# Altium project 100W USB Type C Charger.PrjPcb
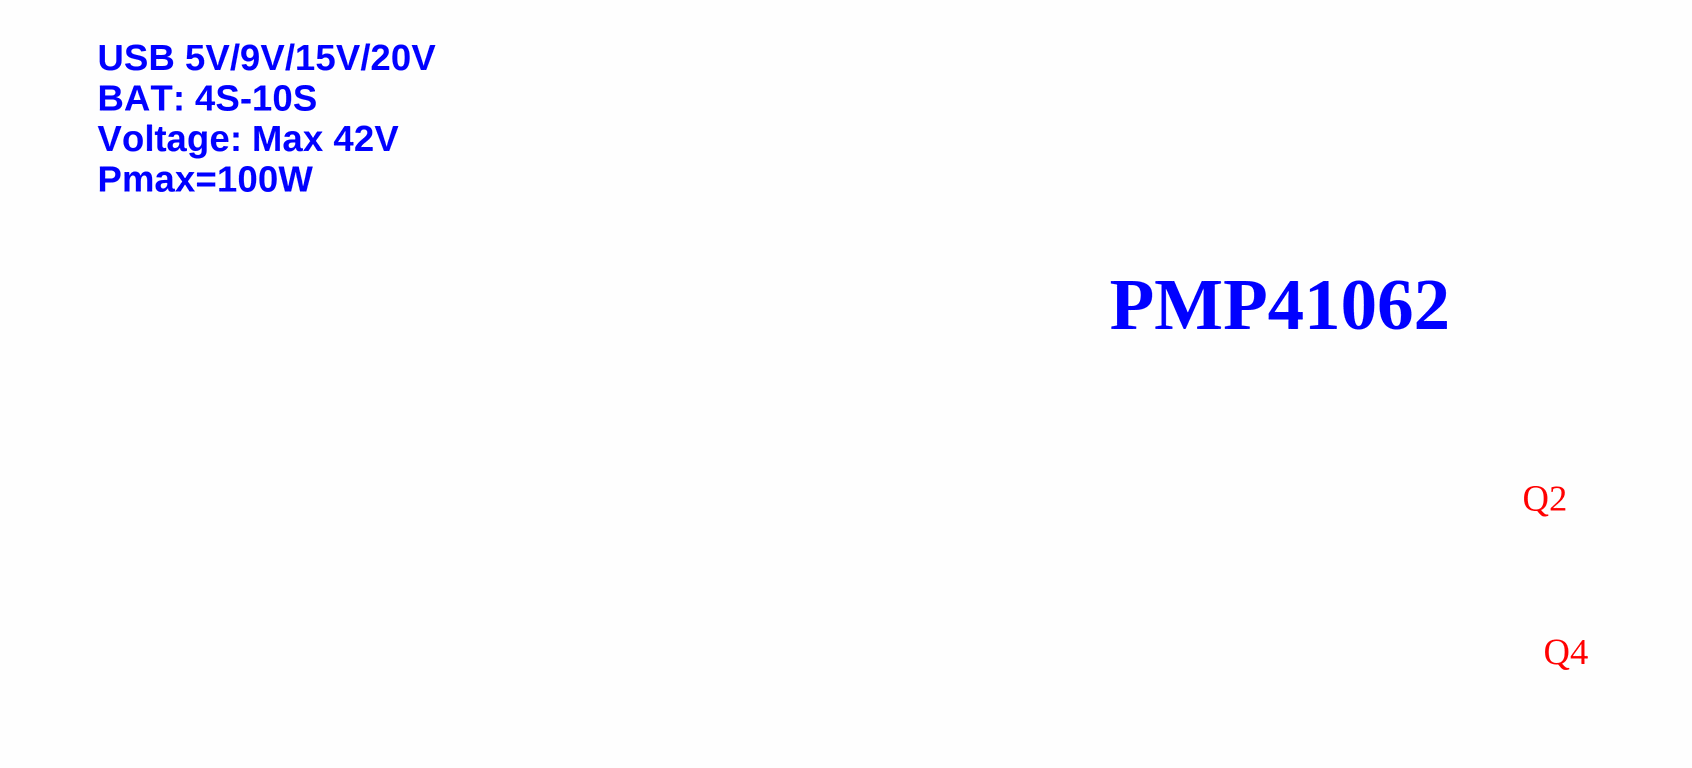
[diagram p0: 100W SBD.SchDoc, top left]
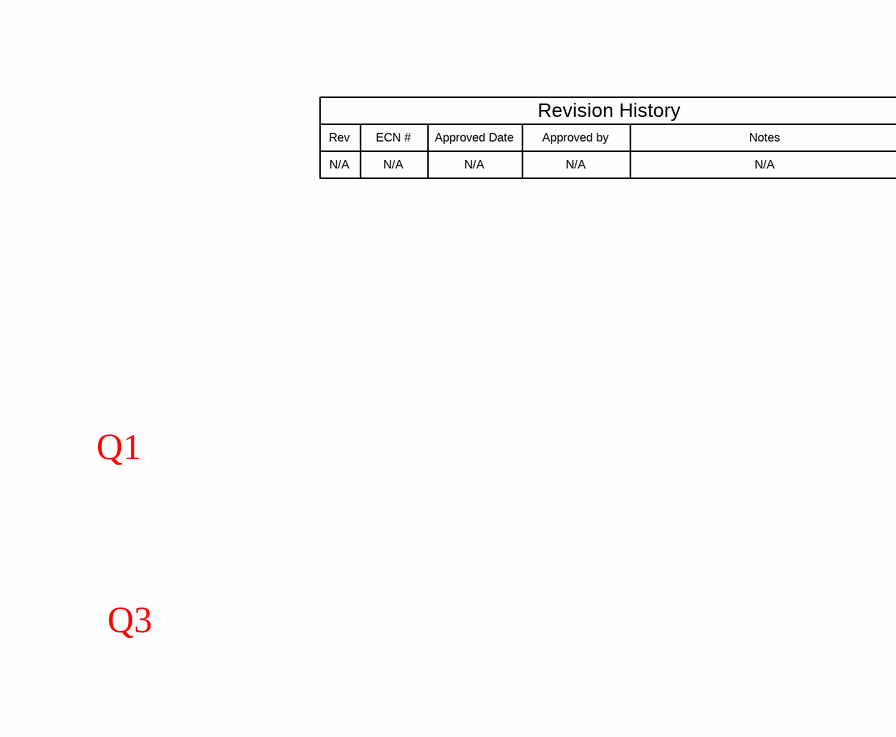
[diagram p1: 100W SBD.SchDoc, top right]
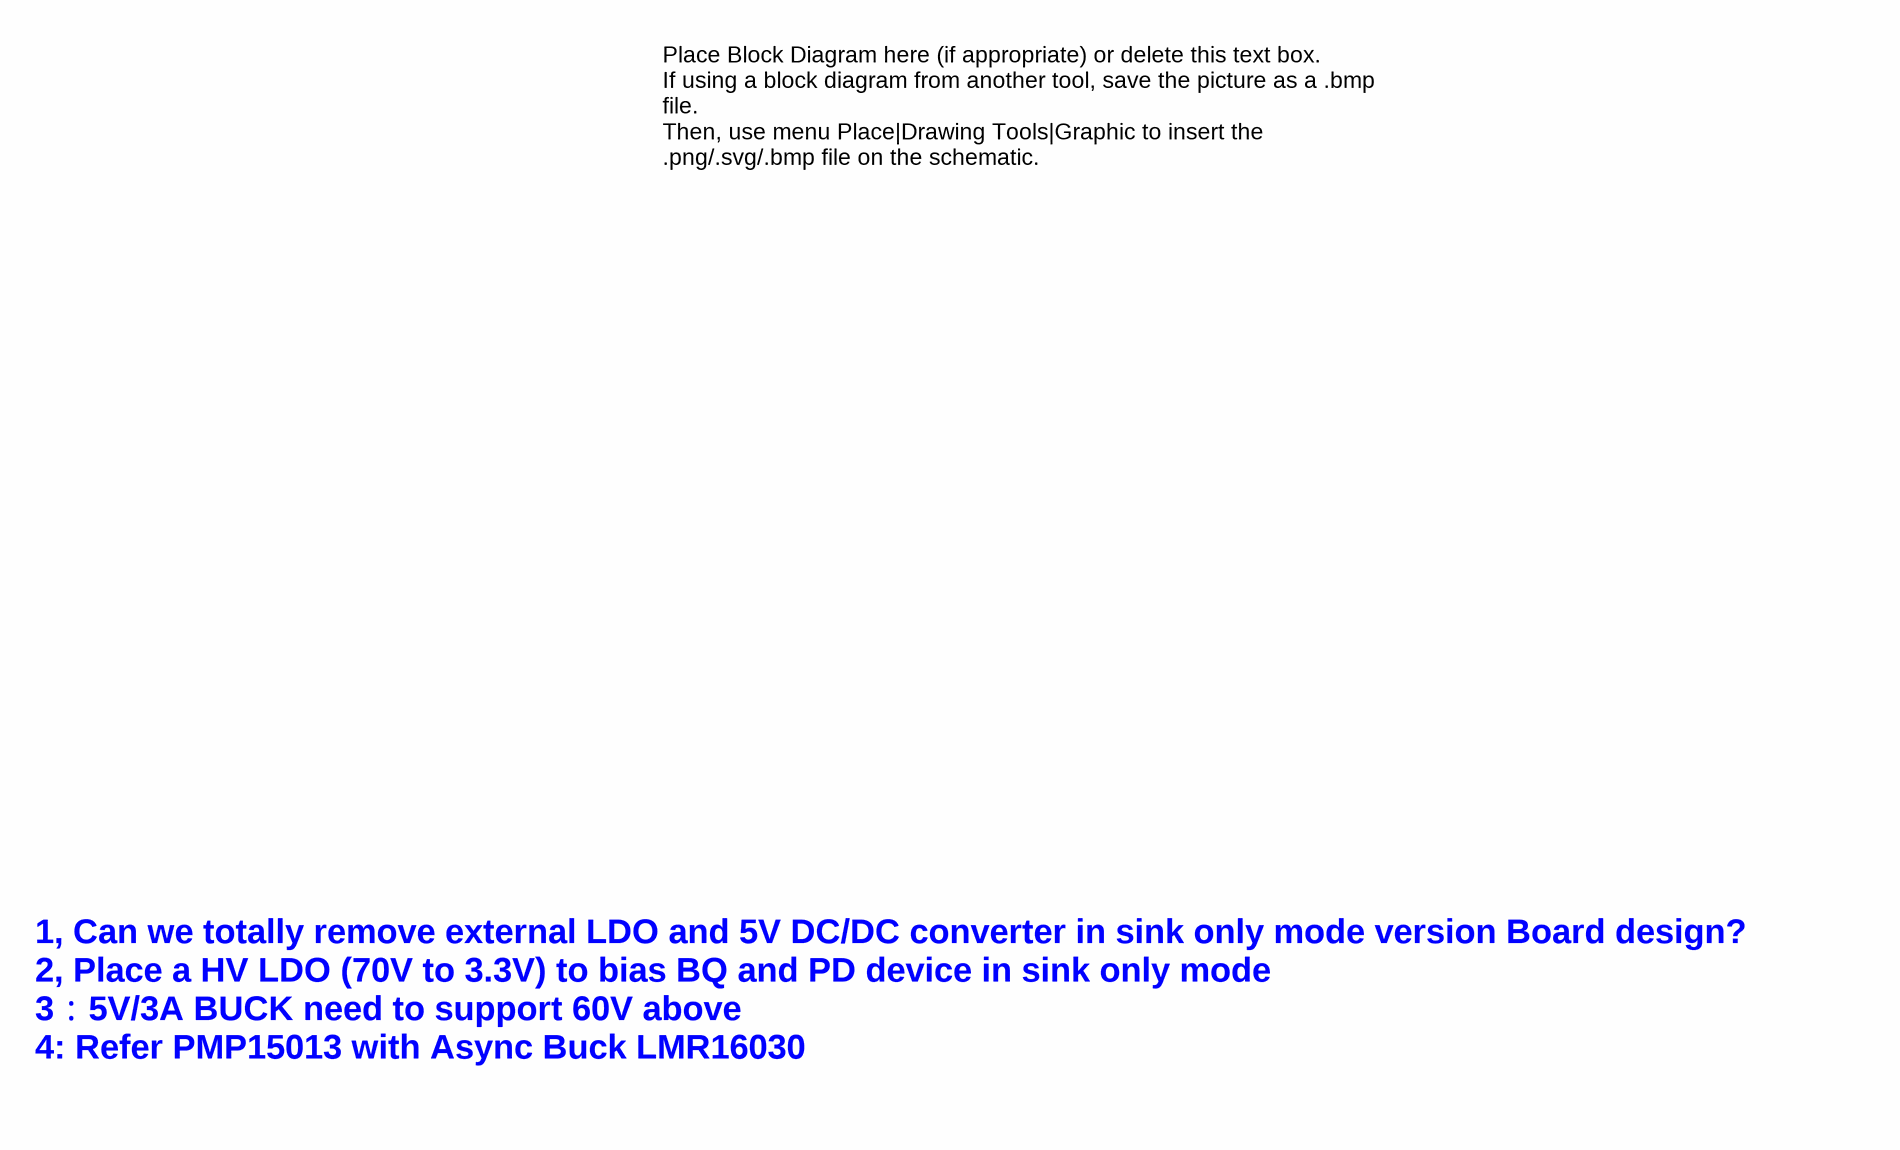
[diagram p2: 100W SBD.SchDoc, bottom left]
CopyrightYear: 2018; PCB_Layout: Max Wang; PCB_Rev: E1; PRJ_Customer: Public Release; PRJ_Engineer: Max Wang; PRJ_Number: PMP41062; PRJ_Title: 100W USB Type C; SCH_Rev: E1; TechSupport: http://www.ti.com/support; TID: PMP41062
4 sheets, 162 parts. Net scope: flat (ports and power ports of the same name join across sheets).
Board file: 100W USB Type C Charger.PcbDoc
Sheets:
  100W SBD.SchDoc
  PD Controller.SchDoc
  Charger BQ25756.SchDoc
  100W USB Type C Charger_Hardware.SchDoc

## Sheet 100W SBD.SchDoc
size A2; Date: Not shown in title block; ApprovedBy: Not shown in title block; CheckedBy: Not shown in title block; Author: Not shown in title block; CompanyName: Not shown in title block; Engineer: Not shown in title block; Organization: Not shown in title block; Address1: Not shown in title block; Address2: Not shown in title block; Address3: Not shown in title block; Address4: Not shown in title block; DocumentNumber: 1; Revision: Use project parameter SCH_Rev; SheetNumber: 1; SheetTotal: 4; PageSetup: Record=PageOptions¦CenterHorizontal=True¦CenterVertical=True¦PrintScale=1.00¦XCorrection=1.00¦YCorrection=1.00¦PrintKind=0¦BorderSize=5000000¦LeftOffset=0¦BottomOffset=0¦Orientation=2¦PaperLength=1000¦PaperWidth=1000¦Scale=100¦PaperSource=15¦PrintQuality=600¦MediaType=1¦DitherType=10¦PaperKind=Letter¦PrintScaleMode=1

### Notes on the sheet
- Revision History
- USB 5V/9V/15V/20V
  BAT: 4S-10S
  Voltage: Max 42V
  Pmax=100W
- Rev
- N/A
- ECN #
- Approved Date
- Approved by
- Notes
- PMP41062
- Q1
- Q2
- Q4
- Q3
- Place Block Diagram here (if appropriate) or delete this text box.
  If using a block diagram from another tool, save the picture as a .bmp file.
  Then, use menu Place|Drawing Tools|Graphic to insert the .png/.svg/.bmp file on the schematic.
- 1, Can we totally remove external LDO and 5V DC/DC converter in sink only mode version Board design?
  2, Place a HV LDO (70V to 3.3V) to bias BQ and PD device in sink only mode
  3：5V/3A BUCK need to support 60V above
  4: Refer PMP15013 with Async Buck LMR16030

## Sheet PD Controller.SchDoc
size A2; Date: Not shown in title block; ApprovedBy: Not shown in title block; CheckedBy: Not shown in title block; Author: Not shown in title block; CompanyName: Not shown in title block; Engineer: Not shown in title block; Organization: Not shown in title block; Address1: Not shown in title block; Address2: Not shown in title block; Address3: Not shown in title block; Address4: Not shown in title block; DocumentNumber: 1; Revision: Use project parameter SCH_Rev; SheetNumber: 2; SheetTotal: 4; PageSetup: Record=PageOptions¦CenterHorizontal=True¦CenterVertical=True¦PrintScale=1.00¦XCorrection=1.00¦YCorrection=1.00¦PrintKind=0¦BorderSize=5000000¦LeftOffset=0¦BottomOffset=0¦Orientation=2¦PaperLength=1000¦PaperWidth=1000¦Scale=100¦PaperSource=15¦PrintQuality=600¦MediaType=1¦DitherType=10¦PaperKind=Letter¦PrintScaleMode=1
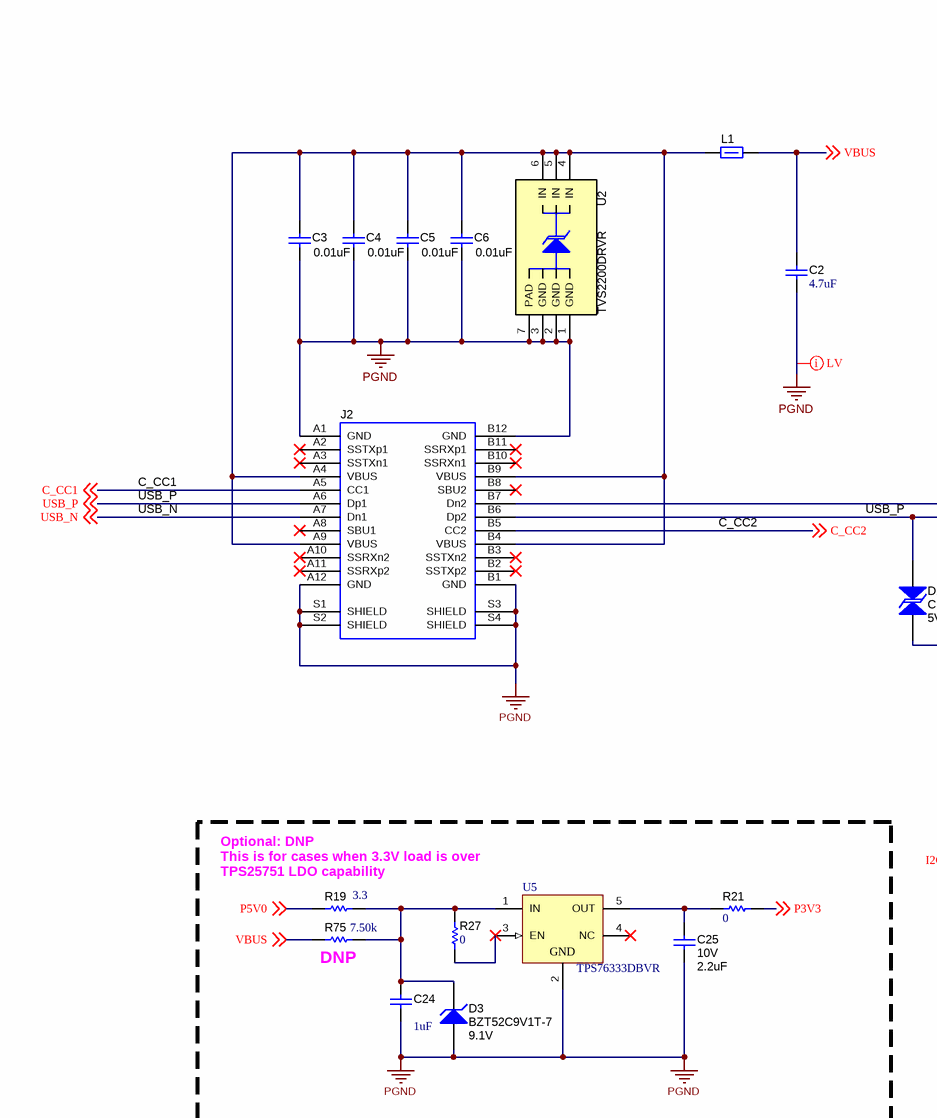
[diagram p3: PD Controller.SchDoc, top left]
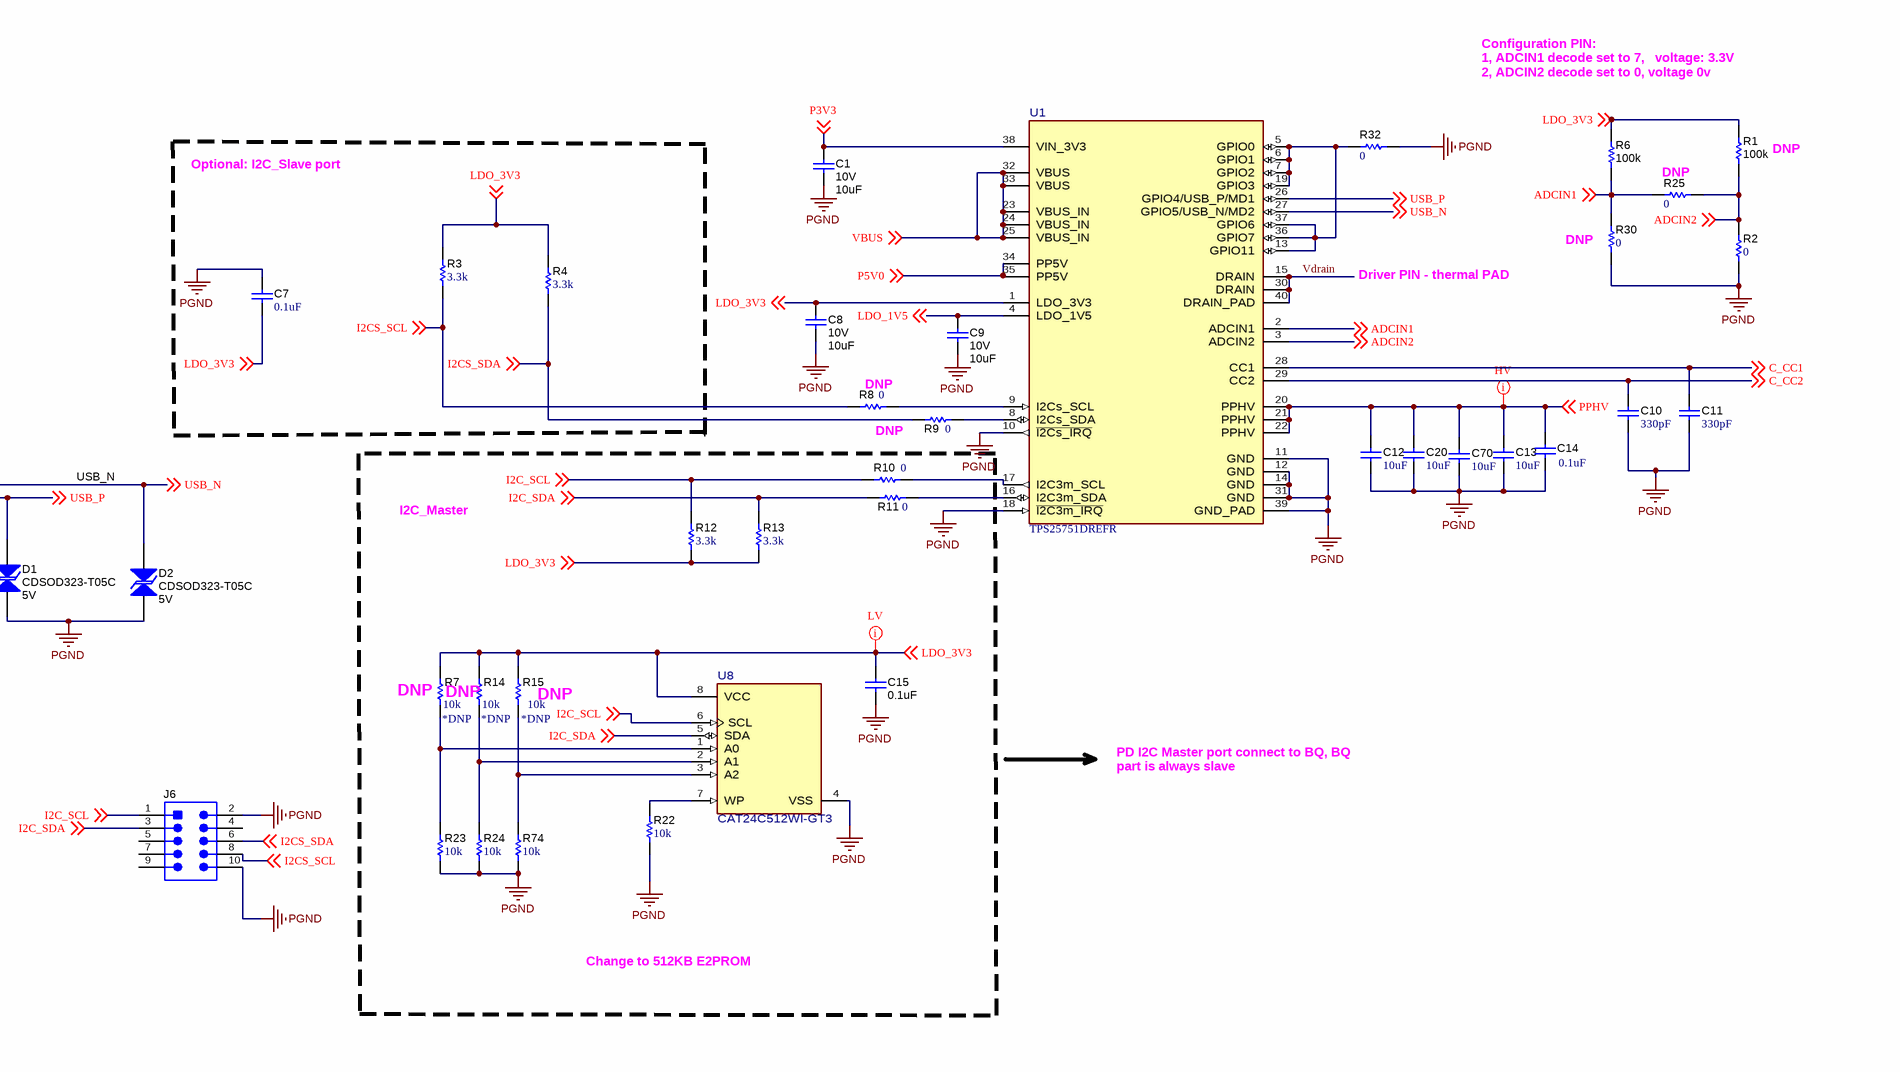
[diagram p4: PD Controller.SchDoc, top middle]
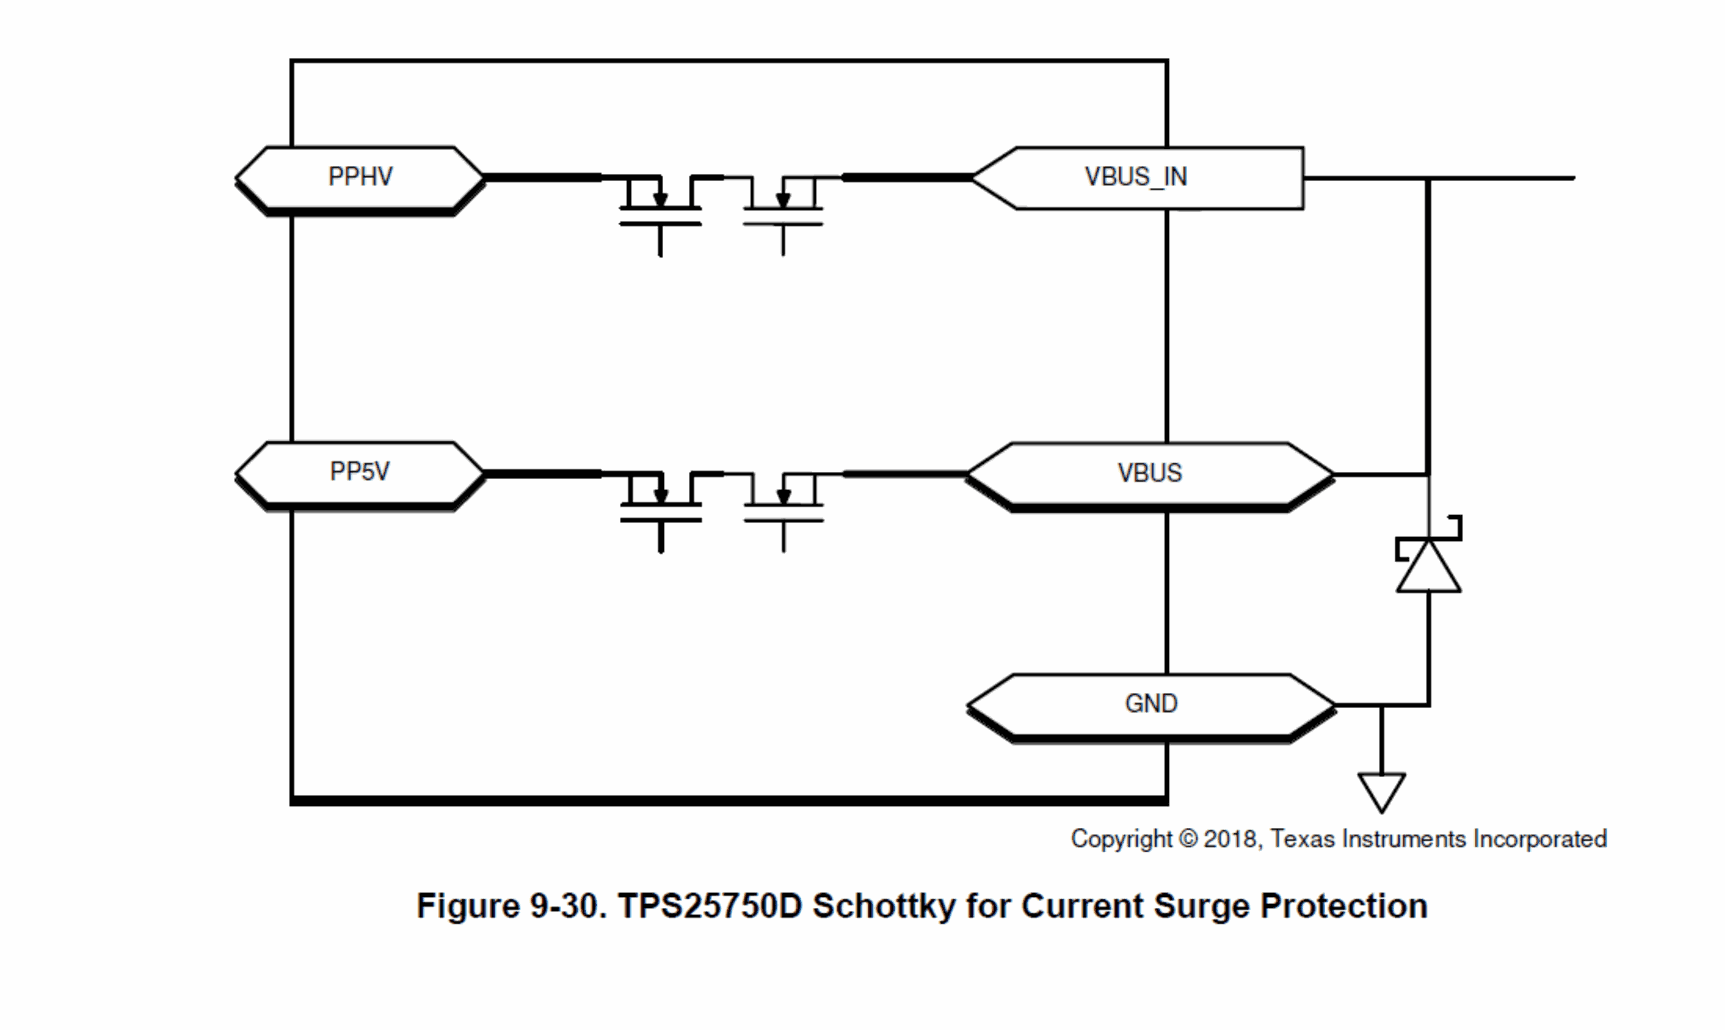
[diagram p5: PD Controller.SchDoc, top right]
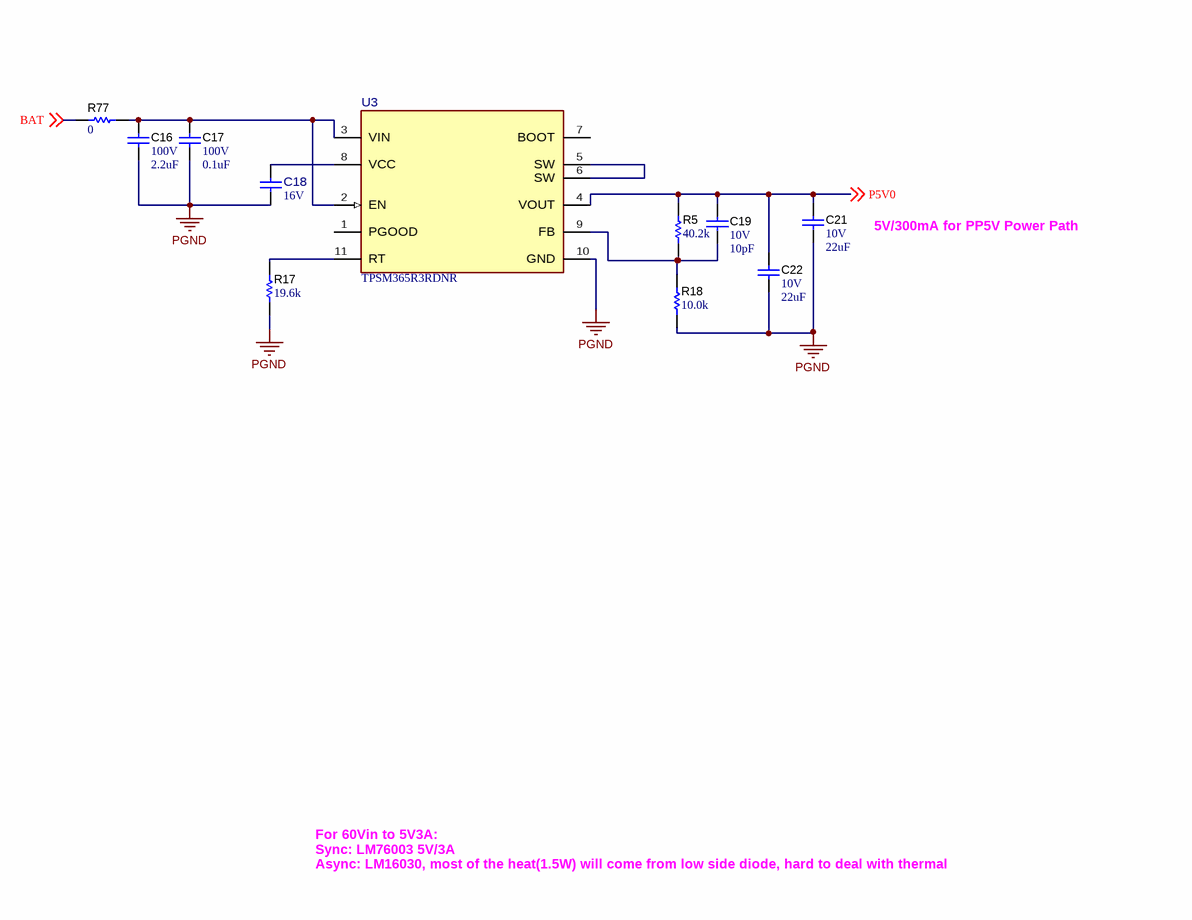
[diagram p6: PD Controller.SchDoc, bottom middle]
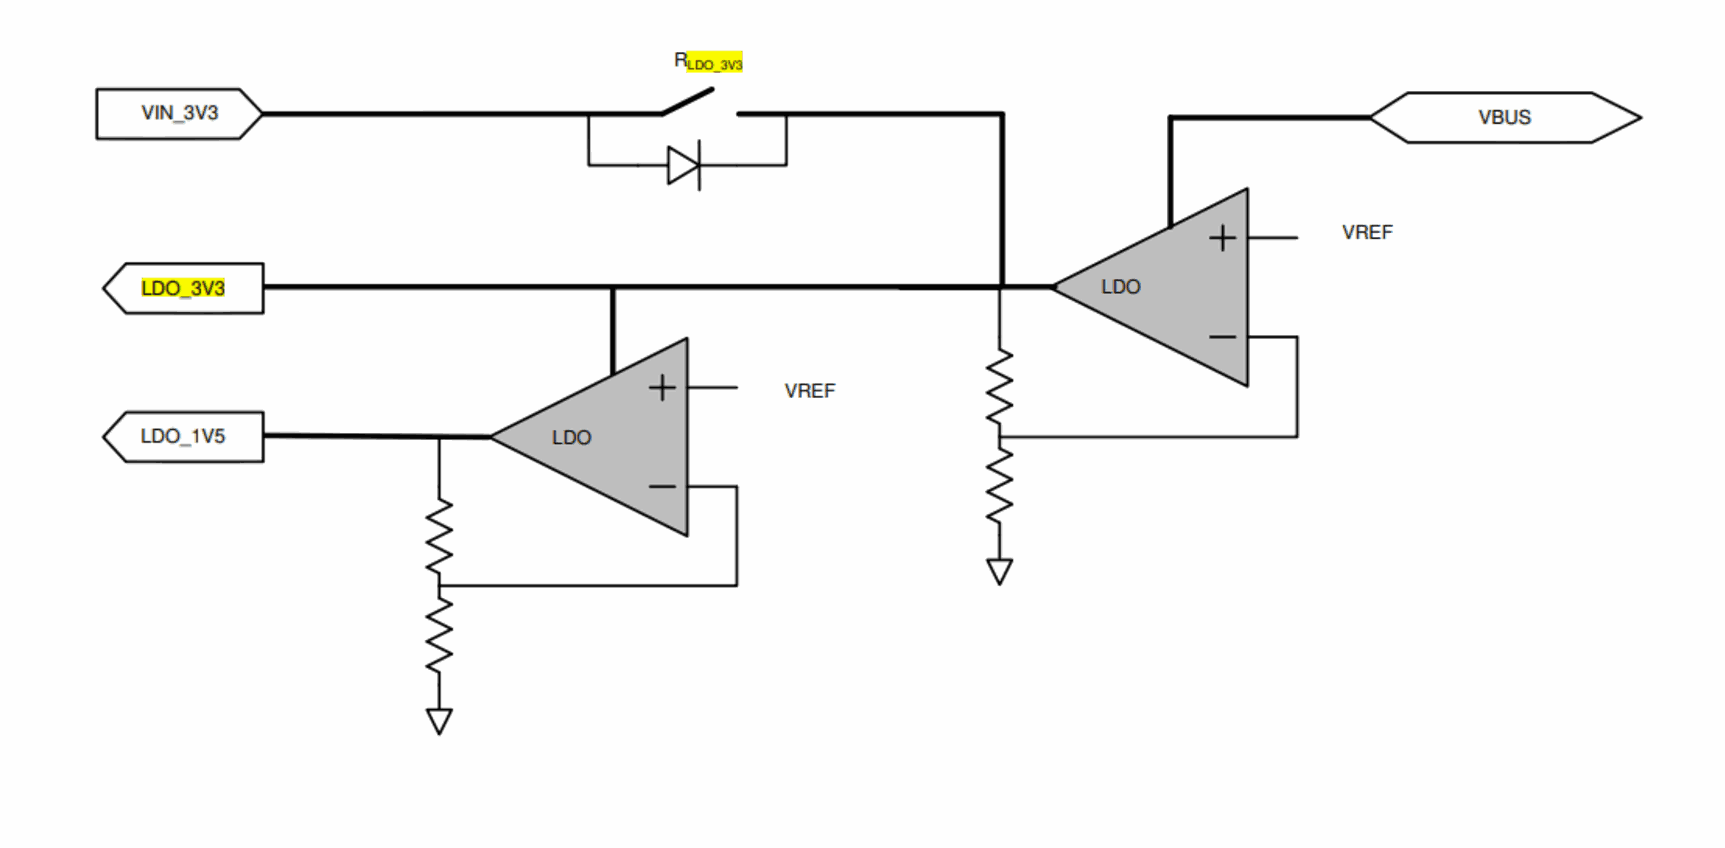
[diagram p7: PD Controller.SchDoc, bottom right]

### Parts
C1  VDC_V: 10V  ValueDisplayed: 10uF  [0402_070]  (hidden comment: CL05A106MP5NUNC)
C2  ValueDisplayed: 4.7uF  [0805_HV]  (hidden comment: GRM21BR61H475KE51L)
C3  ValueDisplayed: 0.01uF  [0402]  (hidden comment: C0402C103J5RACTU)
C4  ValueDisplayed: 0.01uF  [0402]  (hidden comment: C0402C103J5RACTU)
C5  ValueDisplayed: 0.01uF  [0402]  (hidden comment: C0402C103J5RACTU)
C6  ValueDisplayed: 0.01uF  [0402]  (hidden comment: C0402C103J5RACTU)
C7  ValueDisplayed: 0.1uF  [0603]  (hidden comment: CMP-0006808-4)
C8  VDC_V: 10V  ValueDisplayed: 10uF  [0402_070]  (hidden comment: CL05A106MP5NUNC)
C9  VDC_V: 10V  ValueDisplayed: 10uF  [0402_070]  (hidden comment: CL05A106MP5NUNC)
C10  ValueDisplayed: 330pF  [0201_033]  (hidden comment: CGA1A2X7R1H331K030BA)
C11  ValueDisplayed: 330pF  [0201_033]  (hidden comment: CGA1A2X7R1H331K030BA)
C12  ValueDisplayed: 10uF  [1206_180]  (hidden comment: CL31B106KBHNNNE)
C13  ValueDisplayed: 10uF  [1206_180]  (hidden comment: CL31B106KBHNNNE)
C14  ValueDisplayed: 0.1uF  [0603]  (hidden comment: GCM188R71H104KA57D)
C15  ValueDisplayed: 0.1uF  [0402]  (hidden comment: GMK105BJ104KV-F)
C16  VDC_V: 100V  ValueDisplayed: 2.2uF  [1206_180]  (hidden comment: C3216X7S2A225K160AB)
C17  VDC_V: 100V  ValueDisplayed: 0.1uF  [0402]  (hidden comment: GRM155R62A104KE14D)
C18  VDC_V: 16V  [FP-0402YD105KAT2A_0402-IPC_B]  (hidden comment: 0402YD105KAT2A)
C19  VDC_V: 10V  ValueDisplayed: 10pF  [0402]  (hidden comment: C0402C100C8GACTU)
C20  ValueDisplayed: 10uF  [1206_180]  (hidden comment: CL31B106KBHNNNE)
C21  VDC_V: 10V  ValueDisplayed: 22uF  [0603]  (hidden comment: CL10A226MP8NUNE)
C22  VDC_V: 10V  ValueDisplayed: 22uF  [0603]  (hidden comment: CL10A226MP8NUNE)
C24  ValueDisplayed: 1uF  [0805_HV]  (hidden comment: C2012X7S2A105K125AB)
C25  VDC_V: 10V  ValueDisplayed: 2.2uF  [0603]  (hidden comment: CGA3E3X5R1A225K080AB)
C70  ValueDisplayed: 10uF  [1206_180]  (hidden comment: CL31B106KBHNNNE)
D1  CDSOD323-T05C  value 5V  [SOD-323-Bi]
D2  CDSOD323-T05C  value 5V  [SOD-323-Bi]
D3  BZT52C9V1T-7  value 9.1V  [SOD-523]
J2  DX07S024JJ2R1300  [JAE_DX07S024JJ2R1300]  (value not drawn)
J6  PEC05DAAN  [CONN_PEC05DAAN]  (value not drawn)
L1  FBMJ2125HM210NT  [0805_HV]  (value not drawn)
R1  ValueDisplayed: 100k  [0402]  (hidden comment: RMCF0402FT100K)
R2  ValueDisplayed: 0  [0402]  (hidden comment: RC0402JR-070RL)
R3  ValueDisplayed: 3.3k  [0402]  (hidden comment: CRCW04023K30JNED)
R4  ValueDisplayed: 3.3k  [0402]  (hidden comment: CRCW04023K30JNED)
R5  ValueDisplayed: 40.2k  [0603]  (hidden comment: RG1608P-4022-B-T5)
R6  ValueDisplayed: 100k  [0402]  (hidden comment: RMCF0402FT100K)
R7  value 10k  Parameter 1: *DNP  [0402]  (hidden comment: CMP-0026825-5)
R8  ValueDisplayed: 0  [0402]  (hidden comment: CMP-0027004-2)
R9  ValueDisplayed: 0  [0402]  (hidden comment: CMP-0027004-2)
R10  ValueDisplayed: 0  [0402]  (hidden comment: CMP-0027004-2)
R11  ValueDisplayed: 0  [0402]  (hidden comment: CMP-0027004-2)
R12  ValueDisplayed: 3.3k  [0402]  (hidden comment: CRCW04023K30JNED)
R13  ValueDisplayed: 3.3k  [0402]  (hidden comment: CRCW04023K30JNED)
R14  value 10k  Parameter 1: *DNP  [0402]  (hidden comment: CMP-0026825-5)
R15  value 10k  Parameter 1: *DNP  [0402]  (hidden comment: CMP-0026825-5)
R17  ValueDisplayed: 19.6k  [0402]  (hidden comment: CRCW040219K6FKED)
R18  ValueDisplayed: 10.0k  [0402]  (hidden comment: ERJ-2RKF1002X)
R19  ValueDisplayed: 3.3  [0805_HV]  (hidden comment: RC0805JR-073R3L)
R21  ValueDisplayed: 0  [0402]  (hidden comment: CMP-0027004-2)
R22  ValueDisplayed: 10k  [0402]  (hidden comment: CMP-0026825-5)
R23  ValueDisplayed: 10k  [0402]  (hidden comment: CMP-0026825-5)
R24  ValueDisplayed: 10k  [0402]  (hidden comment: CMP-0026825-5)
R25  ValueDisplayed: 0  [0402]  (hidden comment: CMP-0027004-2)
R27  ValueDisplayed: 0  [0402]  (hidden comment: CMP-0027004-2)
R30  ValueDisplayed: 0  [0402]  (hidden comment: RC0402JR-070RL)
R32  ValueDisplayed: 0  [0402]  (hidden comment: RC0402JR-070RL)
R74  ValueDisplayed: 10k  [0402]  (hidden comment: CMP-0026825-5)
R75  ValueDisplayed: 7.50k  [1206]  (hidden comment: RC1206FR-077K5L)
R77  ValueDisplayed: 0  [0402]  (hidden comment: CMP-0027004-2)
U1  TPS25751DREFR  [RJK0038B-MFG]
U2  TVS2200DRVR  [DRV0006A]
U3  TPSM365R3RDNR  [RDN0011A-MFG]
U5  TPS76333DBVR  [DBV0005A_N]
U8  CAT24C512WI-GT3  [FP-CAT24C512WI-GT3_SOIC8-IPC_C]

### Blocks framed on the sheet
DNP: C24 C25 D3 R19 R21 R27 R75 U5

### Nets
PGND: C1.2 C2.2 C3.2 C4.2 C5.2 C6.2 C7.1 C8.1 C9.1 C10.2 C11.2 C12.2 C13.2 C14.2 C15.2 C16.2 C17.2 C18.2 C20.2 C21.2 C22.2 C24.2 C25.2 C70.2 D1.1 D2.1 D3.2(A) J2.A1(GND) J2.A12(GND) J2.B1(GND) J2.B12(GND) J2.S1(SHIELD) J2.S2(SHIELD) J2.S3(SHIELD) J2.S4(SHIELD) J6.2 J6.10 R2.1 R17.1 R18.1 R22.1 R23.1 R24.1 R30.1 R32.2 R74.1 U1.10(~{I2Cs_IRQ}) U1.11(GND) U1.12(GND) U1.14(GND) U1.18(~{I2C3m_IRQ}) U1.31(GND) U1.39(GND_PAD) U2.1(GND) U2.2(GND) U2.3(GND) U2.7(PAD) U3.10(GND) U5.2(GND) U8.4(VSS)
ADCIN1: R6.2 R25.2 R30.2 U1.2(ADCIN1) ; off-sheet ADCIN1
ADCIN2: R1.1 R2.2 R25.1 U1.3(ADCIN2) ; off-sheet ADCIN2
BAT: R77.2 ; off-sheet BAT
C_CC1: C11.1 J2.A5(CC1) U1.28(CC1) ; off-sheet C_CC1
C_CC2: C10.1 J2.B5(CC2) U1.29(CC2) ; off-sheet C_CC2
I2C_SCL: J6.1 R10.2 R12.2 U8.6(SCL) ; off-sheet I2C_SCL
I2C_SDA: J6.3 R11.2 R13.2 U8.5(SDA) ; off-sheet I2C_SDA
I2CS_SCL: J6.8 R3.1 R8.2 ; off-sheet I2CS_SCL
I2CS_SDA: J6.6 R4.1 R9.2 ; off-sheet I2CS_SDA
LDO_1V5: C9.2 U1.4(LDO_1V5) ; off-sheet LDO_1V5
LDO_3V3: C7.2 C8.2 C15.1 R1.2 R3.2 R4.2 R6.1 R7.2 R12.1 R13.1 R14.2 R15.2 U1.1(LDO_3V3) U8.8(VCC) ; off-sheet LDO_3V3
P3V3: C1.1 R21.1 U1.38(VIN_3V3) ; off-sheet P3V3
P5V0: C19.1 C21.1 C22.1 R5.2 R19.2 U1.34(PP5V) U1.35(PP5V) U3.4(VOUT) ; off-sheet P5V0
PPHV: C12.1 C13.1 C14.1 C20.1 C70.1 U1.20(PPHV) U1.21(PPHV) U1.22(PPHV) ; off-sheet PPHV
USB_N: D2.2 J2.A7(Dn1) J2.B7(Dn2) U1.27(GPIO5/USB_N/MD2) ; off-sheet USB_N
USB_P: D1.2 J2.A6(Dp1) J2.B6(Dp2) U1.26(GPIO4/USB_P/MD1) ; off-sheet USB_P
VBUS: C2.1 L1.2 R75.2 U1.23(VBUS_IN) U1.24(VBUS_IN) U1.25(VBUS_IN) U1.32(VBUS) U1.33(VBUS) ; off-sheet VBUS
Vdrain: U1.15(DRAIN) U1.30(DRAIN) U1.40(DRAIN_PAD)
NetC3_1: C3.1 C4.1 C5.1 C6.1 J2.A4(VBUS) J2.A9(VBUS) J2.B4(VBUS) J2.B9(VBUS) L1.1 U2.4(IN) U2.5(IN) U2.6(IN)
NetC16_1: C16.1 C17.1 R77.1 U3.2(EN) U3.3(VIN)
NetC18_1: C18.1 U3.8(VCC)
NetC19_2: C19.2 R5.1 R18.2 U3.9(FB)
NetC24_1: C24.1 D3.1(K) R19.1 R27.2 R75.1 U5.1(IN)
NetC25_1: C25.1 R21.2 U5.5(OUT)
NetR7_1: R7.1 R23.2 U8.1(A0)
NetR8_1: R8.1 U1.9(I2Cs_SCL)
NetR9_1: R9.1 U1.8(I2Cs_SDA)
NetR10_1: R10.1 U1.17(I2C3m_SCL)
NetR11_1: R11.1 U1.16(I2C3m_SDA)
NetR14_1: R14.1 R24.2 U8.2(A1)
NetR15_1: R15.1 R74.2 U8.3(A2)
NetR17_2: R17.2 U3.11(RT)
NetR22_2: R22.2 U8.7(WP)
NetR27_1: R27.1 U5.3(EN)
NetR32_1: R32.1 U1.5(GPIO0) U1.6(GPIO1) U1.7(GPIO2) U1.13(GPIO11) U1.19(GPIO3) U1.36(GPIO7) U1.37(GPIO6)
NetU3_5: U3.5(SW) U3.6(SW)

Not connected (* = marked no-connect by the designer): J2 A2(SSTXp1)* A3(SSTXn1)* A8(SBU1)* A10(SSRXn2)* A11(SSRXp2)* B2(SSTXp2)* B3(SSTXn2)* B8(SBU2)* B10(SSRXn1)* B11(SSRXp1)*; J6 4 5 7 9; U3 1(PGOOD) 7(BOOT); U5 4(NC)*

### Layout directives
net class LV: LDO_3V3, PGND
net class HV: PPHV

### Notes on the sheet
- Configuration PIN:
  1, ADCIN1 decode set to 7,   voltage: 3.3V
  2, ADCIN2 decode set to 0, voltage 0v
- Optional: I2C_Slave port
- (near R25) DNP
- (near R1) DNP
- (near R30) DNP
- Driver PIN - thermal PAD
- (near R8) DNP
- (near R9) DNP
- I2C_Master
- (near R7) DNP
- (near R14) DNP
- (near R15) DNP
- PD I2C Master port connect to BQ, BQ part is always slave
- Optional: DNP
  This is for cases when 3.3V load is over TPS25751 LDO capability
- Change to 512KB E2PROM
- 5V/300mA for PP5V Power Path
- For 60Vin to 5V3A:
  Sync: LM76003 5V/3A
  Async: LM16030, most of the heat(1.5W) will come from low side diode, hard to deal with thermal

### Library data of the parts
C1 C8 C9 = CMP-0006339-4: CAP, CERM, 10 uF, 10 V, +/- 20%, X5R, 0402; Manufacturer: Samsung Electro-Mechanics; TaMin_C: -55°C; Polarized: N; SizeAreaWB_mm2: 3; Value1: Unknown; U/M: EA; Value: 10uF; TaMax_C: 85°C; SizeZ_mm: 0.6; SizeX_mm: 1; SizeY_mm: 0.5; Cap_Case: 0402; Cap_F: 10µF; AEC Category: Q200
C2 = CMP-0008309-2: CAP, CERM, 4.7 uF, 50 V, +/- 10%, X5R, 0805; Manufacturer: MuRata; TaMin_C: -55°C; Polarized: N; SizeAreaWB_mm2: 6.75; Value1: Unknown; U/M: EA; Value: 4.7uF; TaMax_C: 85°C; SizeZ_mm: 1.45; SizeX_mm: 2; SizeY_mm: 1.25; Cap_Case: 0805; Value2: 50V; SizeArea_mm2: 2.5; Cap_F: 4.7µF; AEC Category: Q200
C3-C6 = CMP-0006236-2: CAP, CERM, 0.01 uF, 50 V, +/- 5%, X7R, 0402; Manufacturer: Kemet; TaMin_C: -55°C; Polarized: N; SizeAreaWB_mm2: 3; Value1: Unknown; U/M: EA; Value: 0.01uF; TaMax_C: 125°C; SizeZ_mm: 0.6; SizeX_mm: 1; SizeY_mm: 0.5; Value2: 50V; CompType: Capacitor; Cap_F: 10nF; AEC Category: Q200
C7 = CMP-0006808-4: CAP, CERM, 0.1 uF, 16 V, +/- 5%, X7R, 0603; PartNumber: 0603YC104JAT2A; Manufacturer: AVX; Polarized: N; Value: 0.1uF; U/M: EA; Cap_F: 100nF; ESR_ohm: 39m; Value1: 0.039 ohm; VDC_V: 16V; TaMin_C: -55°C; TaMax_C: 125°C; SizeArea_mm2: 1.28; SizeAreaWB_mm2: 4.68; SizeX_mm: 1.6; SizeY_mm: 0.8; SizeZ_mm: 1; AEC Category: Q200
C10 C11 = CMP-0009653-3: CAP, CERM, 330 pF, 50 V, +/- 10%, X7R, AEC-Q200 Grade 1, 0201; Manufacturer: TDK; TaMin_C: -55°C; ESR_ohm: 8.053; Polarized: N; SizeAreaWB_mm2: 2.08; Value1: 8.05302 ohm; U/M: EA; Value: 330pF; TaMax_C: 125°C; SizeZ_mm: 0.33; SizeX_mm: 0.6; SizeY_mm: 0.3; Value2: 50V; SizeArea_mm2: 0.18; AEC Qualified: Y; IRMS_A: 210.618mA; AEC Grade: 1; AEC Category: Q200
C12 C13 C20 C70 = CMP-0008802-2: CAP, CERM, 10 uF, 50 V, +/- 10%, X7R, 1206; Manufacturer: Samsung; TaMin_C: -55°C; Polarized: N; SizeAreaWB_mm2: 10.92; Value1: Unknown; U/M: EA; Value: 10uF; TaMax_C: 125°C; SizeZ_mm: 1.8; SizeX_mm: 3.2; SizeY_mm: 1.6; Cap_Case: 1206; Value2: 50V; SizeArea_mm2: 5.12; Cap_F: 10µF; AEC Category: Q200
C14 = CMP-0007144-4: CAP, CERM, 0.1 uF, 50 V, +/- 10%, X7R, 0603; Manufacturer: MuRata; TaMin_C: -55°C; Polarized: N; SizeAreaWB_mm2: 4.68; Value1: 0.02 ohm; U/M: EA; Value: 0.1uF; TaMax_C: 125°C; SizeZ_mm: 1; SizeX_mm: 1.6; SizeY_mm: 0.8; Value2: 50V; SizeArea_mm2: 1.28; Cap_F: 100nF; AEC Category: Q200; ESR_ohm: 20m; IRMS_A: 1.84A
C15 = CMP-0006370-2: CAP, CERM, 0.1 uF, 35 V, +/- 10%, X5R, 0402; Manufacturer: Taiyo Yuden; TaMin_C: -55°C; Polarized: N; SizeAreaWB_mm2: 3; Value1: Unknown; U/M: EA; Value: 0.1uF; TaMax_C: 85°C; SizeZ_mm: 0.6; SizeX_mm: 1; SizeY_mm: 0.5; Value2: 35V; CompType: Capacitor; Cap_F: 100nF; AEC Category: Q200
C16 = CMP-0008724-2: CAP, CERM, 2.2 uF, 100 V, +/- 10%, X7S, 1206; Manufacturer: TDK; TaMin_C: -55°C; ESR_ohm: 5.718m; Polarized: N; SizeAreaWB_mm2: 10.92; Value1: 0.005718 ohm; U/M: EA; Value: 2.2uF; TaMax_C: 125°C; SizeZ_mm: 1.8; SizeX_mm: 3.2; SizeY_mm: 1.6; SizeArea_mm2: 5.12; Cap_F: 2.2µF; IRMS_A: 3.0363A; AEC Category: Q200
C17 = CMP-0006618-1: CAP, CERM, 0.1 uF, 100 V, +/- 10%, X5R, 0402; Manufacturer: MuRata; TaMin_C: -55°C; Polarized: N; SizeAreaWB_mm2: 3; Value1: Unknown; U/M: EA; Value: 0.1uF; TaMax_C: 85°C; SizeZ_mm: 0.6; SizeX_mm: 1; SizeY_mm: 0.5; Cap_F: 100nF; AEC Category: Q200
C18 = CMP-00860000-2: CAPACITOR, X5R, 0402, 16V, 1UF; Manufacturer: AVX; SizeZ_mm: 0.56mm; Value: 1µF; TempCo: 15%; Tolerance_%: 10%; AEC Qualified: No; Symbol Name: SYM-0402YD105KAT2A
C19 = CMP-0064914-1: CAP, CERM, 10 pF, 10 V,+/- 2.5%, C0G/NP0, 0402; Manufacturer: Kemet; TaMin_C: -55°C; Polarized: N; SizeAreaWB_mm2: 3; Value1: Unknown; U/M: EA; Value: 10pF; TaMax_C: 125°C; SizeZ_mm: 0.6; SizeX_mm: 1; SizeY_mm: 0.5; AEC Category: Q200
C21 C22 = CMP-0007108-2: CAP, CERM, 22 uF, 10 V, +/- 20%, X5R, 0603; Manufacturer: Samsung Electro-Mechanics; TaMin_C: -55°C; Polarized: N; SizeAreaWB_mm2: 4.68; Value1: Unknown; U/M: EA; Value: 22uF; TaMax_C: 85°C; SizeZ_mm: 1; SizeX_mm: 1.6; SizeY_mm: 0.8; SizeArea_mm2: 1.28; Cap_F: 22µF; AEC Category: Q200
C24 = CMP-0007891-2: CAP, CERM, 1 uF, 100 V, +/- 10%, X7S, 0805; Manufacturer: TDK; TaMin_C: -55°C; Polarized: N; SizeAreaWB_mm2: 6.75; Value1: 0.008255 ohm; U/M: EA; Value: 1uF; TaMax_C: 125°C; SizeZ_mm: 1.45; SizeX_mm: 2; SizeY_mm: 1.25; Cap_Case: 0805; Value2: 100V; SizeArea_mm2: 2.5; Cap_F: 1µF; AEC Category: Q200; ESR_ohm: 8.255m; IRMS_A: 2.2744A
C25 = CMP-0007091-5: CAP, CERM, 2.2 uF, 10 V, +/- 10%, X5R, AEC-Q200 Grade 3, 0603; Manufacturer: TDK; TaMin_C: -55°C; Polarized: N; SizeAreaWB_mm2: 4.68; Value1: Unknown; U/M: EA; Value: 2.2uF; TaMax_C: 85°C; SizeZ_mm: 1; SizeX_mm: 1.6; SizeY_mm: 0.8; SizeArea_mm2: 1.28; AEC Qualified: Y; Cap_F: 2.2µF; AEC Grade: 3; AEC Category: Q200
D1 D2 = CMP-0006065-2: Diode, TVS, Bi, 5 V, SOD323, 2-Leads, Body 1.9x1.45mm, No Polarity Mark; Manufacturer: Bourns; Ppk: 350W; AEC Category: Q101
D3 = CMP-0005905-4: Diode, Zener, 9.1 V, 300 mW, SOD-523; Manufacturer: Diodes Inc.; SizeAreaWB_mm2: 5.13; RJA_CperW: 417; SizeZ_mm: 0.65; SizeArea_mm2: 1.53; AEC Category: Q101; Value1: 0.3W; SizeX_mm: 1.7; SizeY_mm: 0.9; Power_W: 300mW
J2 = CMP-0085712-2: Receptacle, USB 3.1 Type C, R/A, Gold, SMT; Manufacturer: JAE Electronics; Current_A: 1.25A; Gender: Female; Voltage_V: 20V; Pitch_mm: 0.5; Row_Count: 2
J6 = CMP-0054550-2: Header, 100mil, 5x2, Tin, TH; Manufacturer: Sullins Connector Solutions; Current_A: 3A; Green_Lifecycle: Active; Shrouded: N; Gender: Male; Green_REACh: Passed; Voltage_V: 1.8kV; Row_Count: 2; RowSpacing_mm: 2.54; Cert_UL: Y
L1 = CMP-0003375-1: Ferrite Bead, 21 ohm @ 100 MHz, 6 A, 0805; Manufacturer: Taiyo Yuden; ZTyp@100MHz_Ohm: 21; SizeAreaWB_mm2: 6.75; DCR_ohm: 4m; Value1: 0.004 ohm; Value: 21 ohm; Imax_A: 6A; SizeZ_mm: 1.45; SizeX_mm: 2; SizeY_mm: 1.25; SizeArea_mm2: 2.5
R1 R6 = CMP-0026753-1: RES, 100 k, 1%, 0.063 W, AEC-Q200 Grade 0, 0402; Manufacturer: Stackpole Electronics Inc; Power_W: 63mW; TempCo: 100 ppm/C; U/M: EA; Value: 100k; EIA_Code: E96; SizeX_mm: 1; SizeY_mm: 0.5; SizeZ_mm: 0.6; Value2: 0.063W; AEC Qualified: Y; VDC_V: 50V; AEC Grade: 0; AEC Category: Q200
R2 R30 R32 = CMP-0027004-1: RES, 0, 5%, 0.063 W, 0402; Manufacturer: Yageo America; Power_W: 63mW; TempCo: 200 ppm/C; Value_Code: 0000; U/M: EA; Value: 0; EIA_Code: E24; SizeX_mm: 1; SizeY_mm: 0.5; SizeZ_mm: 0.6; Value2: 0.063W; VDC_V: 50V; AEC Category: Q200
R3 R4 R12 R13 = CMP-0026918-5: RES, 3.3 k, 5%, 0.063 W, AEC-Q200 Grade 0, 0402; Manufacturer: Vishay-Dale; Value: 3.3k; Value_Code: 3k30; Power_W: 63mW; Value2: 0.063W; VDC_V: 50V; TempCo: 200 ppm/C; SizeArea_mm2: 0.5; SizeX_mm: 1; SizeZ_mm: 0.6; EIA_Code: E24; AEC Category: Q200; AEC Qualified: Y; AEC Grade: 0
R5 = CMP-0023541-1: RES, 40.2 k, 0.1%, 0.1 W, 0603; Manufacturer: Susumu Co Ltd; Power_W: 100mW; TempCo: 25 ppm/C; Value_Code: 40k2; U/M: EA; Value: 40.2k; EIA_Code: E192; SizeX_mm: 1.6; SizeY_mm: 0.8; SizeZ_mm: 1; Value2: 0.1W; SizeArea_mm2: 1.28; VDC_V: 75V; AEC Category: Q200
R7 R14 R15 = CMP-0026825-5: RES, 10 k, 5%, 0.063 W, AEC-Q200 Grade 0, 0402; PartNumber: CRCW040210K0JNED; Manufacturer: Vishay-Dale; Value_Code: 10k0; Power_W: 63mW; Value2: 0.063W; VDC_V: 50V; TempCo: 200 ppm/C; SizeArea_mm2: 0.5; SizeX_mm: 1; SizeZ_mm: 0.6; EIA_Code: E24; AEC Category: Q200; AEC Qualified: Y; AEC Grade: 0
R8-R11 R21 R25 R27 R77 = CMP-0027004-2: RES, 0, 5%, 0.063 W, 0402; PartNumber: RC0402JR-070RL; Manufacturer: Yageo America; Value: 0; Value_Code: 0000; Power_W: 63mW; Value2: 0.063W; VDC_V: 50V; TempCo: 200 ppm/C; SizeArea_mm2: 0.5; SizeX_mm: 1; SizeZ_mm: 0.6; EIA_Code: E24; U/M: EA; AEC Category: Q200
R17 = CMP-0026068-2: RES, 19.6 k, 1%, 0.063 W, 0402; Manufacturer: Vishay-Dale; Power_W: 63mW; TempCo: 100 ppm/C; Value_Code: 19k6; U/M: EA; Value: 19.6k; EIA_Code: E96; SizeX_mm: 1; SizeY_mm: 0.5; SizeZ_mm: 0.6; Value2: 0.063W; VDC_V: 50V; AEC Category: Q200
R18 = CMP-0026658-1: RES, 10.0 k, 1%, 0.1 W, 0402; Manufacturer: Panasonic; Power_W: 100mW; TempCo: 100 ppm/C; Value_Code: 10k0; U/M: EA; Value: 10.0k; EIA_Code: E96; Res_ohm: 10k; SizeX_mm: 1; SizeY_mm: 0.5; SizeZ_mm: 0.6; Value2: 0.1W; VDC_V: 50V; AEC Category: Q200
R19 = CMP-0020817-2: RES, 3.3, 5%, 0.125 W, 0805; Manufacturer: Yageo America; Value: 3.3; Value_Code: 3R30; Power_W: 125mW; Value2: 0.125W; VDC_V: 150V; TempCo: 200 ppm/C; SizeArea_mm2: 2.5; SizeX_mm: 2; SizeY_mm: 1.25; SizeZ_mm: 1.45; EIA_Code: E24; U/M: EA; AEC Category: Q200
R22-R24 R74 = CMP-0026825-5: RES, 10 k, 5%, 0.063 W, AEC-Q200 Grade 0, 0402; PartNumber: CRCW040210K0JNED; Manufacturer: Vishay-Dale; Value: 10k; Value_Code: 10k0; Power_W: 63mW; Value2: 0.063W; VDC_V: 50V; TempCo: 200 ppm/C; SizeArea_mm2: 0.5; SizeX_mm: 1; SizeZ_mm: 0.6; EIA_Code: E24; AEC Category: Q200; AEC Qualified: Y; AEC Grade: 0
R75 = CMP-0018483-2: RES, 7.50 k, 1%, 0.25 W, 1206; Manufacturer: Yageo America; Value: 7.50k; Res_ohm: 7.5k; Value_Code: 7k50; Power_W: 250mW; Value2: 0.25W; VDC_V: 200V; TempCo: 100 ppm/C; SizeArea_mm2: 5.12; SizeX_mm: 3.2; SizeY_mm: 1.6; SizeZ_mm: 1.35; EIA_Code: E96; U/M: EA; AEC Category: Q200
U1 = CMP-0098263-1: USB Type-C and USB PD Controller with Integrated Power Switches Optimized for Power Applications; Manufacturer: Texas Instruments; AEC Qualified: No; Usb Standard: USB 3.0; SizeZ_mm: 0.8mm; Number Of Ports: 1; Standoff Height: 0mm; Interface: I2C,USB
U2 = CMP-0077834-1: 22-V Precision Surge Protection Clamp, DRV0006A (WSON-6); Alternate Manufacturer: Texas Instruments; SizeAreaWB_mm2: 9.0; SizeZ_mm: 0.8; SizeX_mm: 2.0; SizeArea_mm2: 4.0; CompType: IC; AEC Qualified: N; AEC Category: Q200
U3 = CMP-0097147-1: 3-V to 65-V Input, 1-V to 13-V Output, 600-mA Synchronous Buck Converter Power Module in a HotRod QFN Package; Manufacturer: Texas Instruments; SizeZ_mm: 2.1mm; AEC Qualified: No; Max Duty Cycle: 98%; Max Supply Voltage: 65V; Min Supply Voltage: 3.6V; Nominal Supply Current: 17-18uA; Number Of Outputs: 1; Output Type: AdjustableProgrammable; Output Voltage: 1-13V; Standoff Height: 0mm; Switching Frequency: 200-2200kHz; TJmax_C: +125°C
U5 = CMP-0035539-1: Single Output LDO, 150 mA, Fixed 3.3 V Output, 2.7 to 10 V Input, with Low IQ, 5-pin SOT-23 (DBV), -40 to 125 degC, Green (RoHS & no Sb/Br); Manufacturer: Texas Instruments; Fixed Output Options(V): 3.3; SubFamily: Single Channel LDO; Vdo(Typ)(mV): 300; Accuracy(%): 3; Vin(Max)(V): 10; Iq(Typ)(mA): 0.08; Vin(Min)(V): 2.7; Iout(Max)(A): 0.15
U8 = CMP-0091847-1: EEPROM Memory IC 512Kb (64K x 8) I²C 1MHz 900ns 8-SOIC; Manufacturer: ON Semi; Standoff Height: 0.1mm; AEC Qualified: No; Max Supply Voltage: 5.5V; Interface: I2C; SizeZ_mm: 1.75mm; Memory Size: 512Kbits; Min Supply Voltage: 1.8V

## Sheet Charger BQ25756.SchDoc
size A2; Date: Not shown in title block; ApprovedBy: Not shown in title block; CheckedBy: Not shown in title block; Author: Not shown in title block; CompanyName: Not shown in title block; Engineer: Not shown in title block; Organization: Not shown in title block; Address1: Not shown in title block; Address2: Not shown in title block; Address3: Not shown in title block; Address4: Not shown in title block; DocumentNumber: 1; Revision: Use project parameter SCH_Rev; SheetNumber: 3; SheetTotal: 4; PageSetup: Record=PageOptions¦CenterHorizontal=True¦CenterVertical=True¦PrintScale=0.69¦XCorrection=1.00¦YCorrection=1.00¦PrintKind=0¦BorderSize=5000000¦LeftOffset=0¦BottomOffset=0¦Orientation=2¦PaperLength=1000¦PaperWidth=1000¦Scale=100¦PaperSource=15¦PrintQuality=600¦MediaType=1¦DitherType=10¦PaperKind=Letter¦PrintScaleMode=1
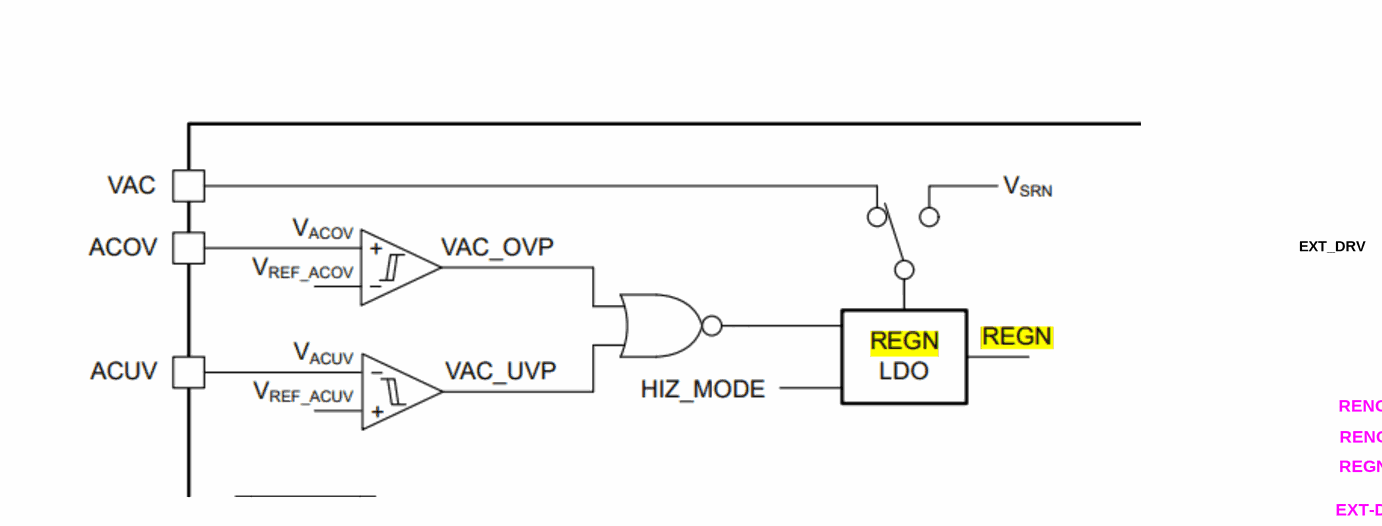
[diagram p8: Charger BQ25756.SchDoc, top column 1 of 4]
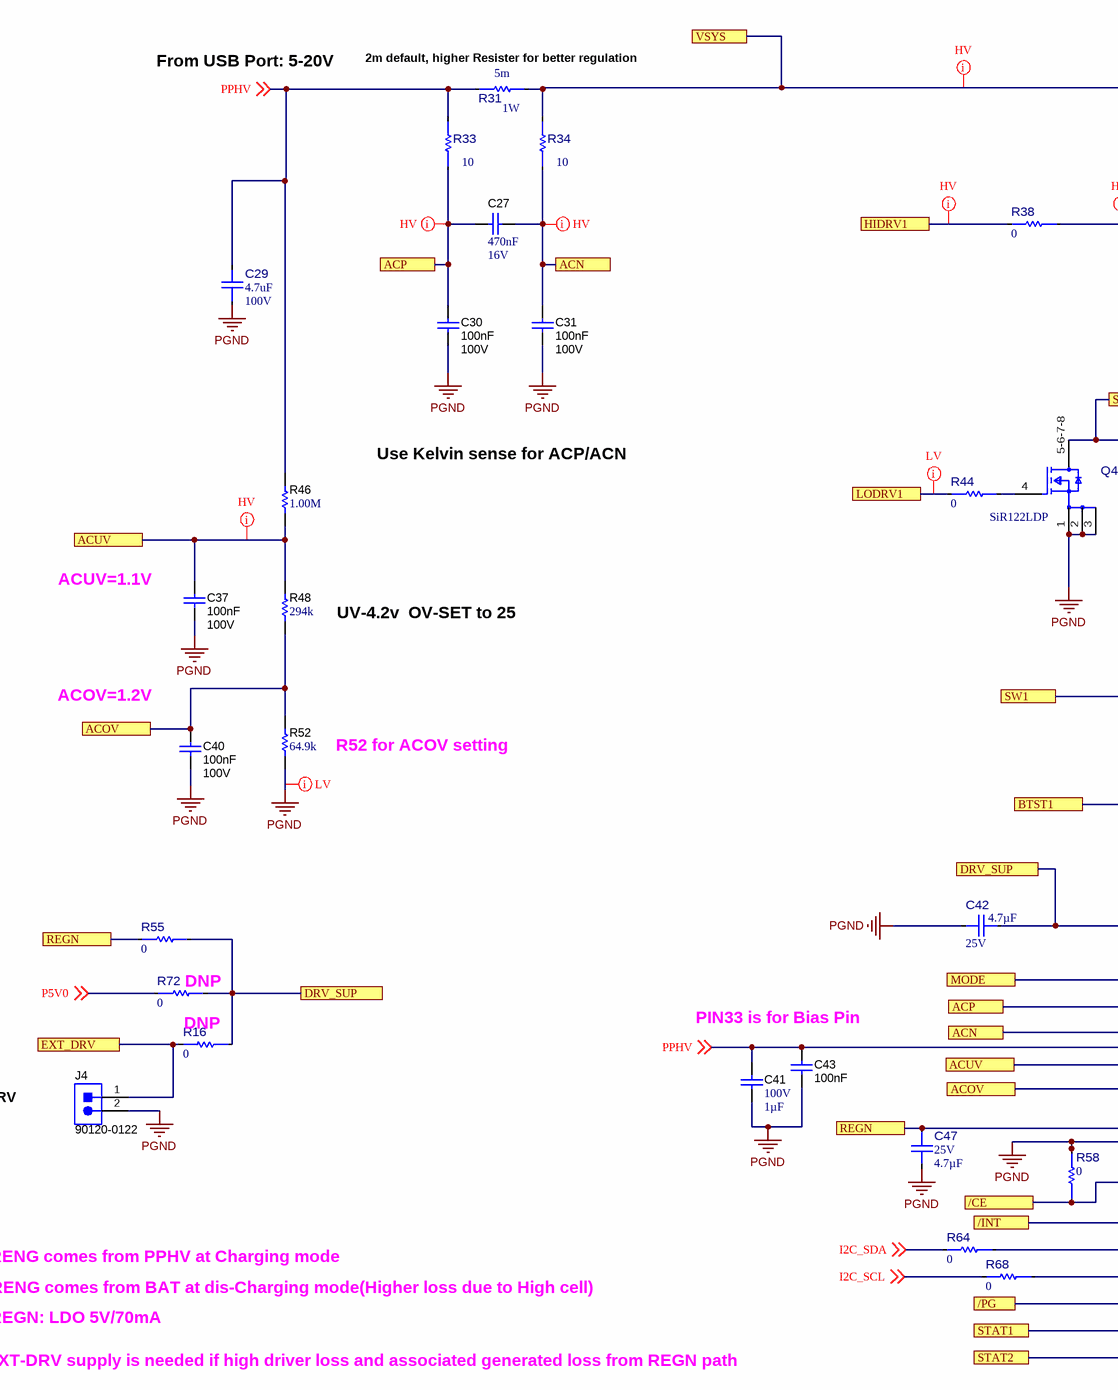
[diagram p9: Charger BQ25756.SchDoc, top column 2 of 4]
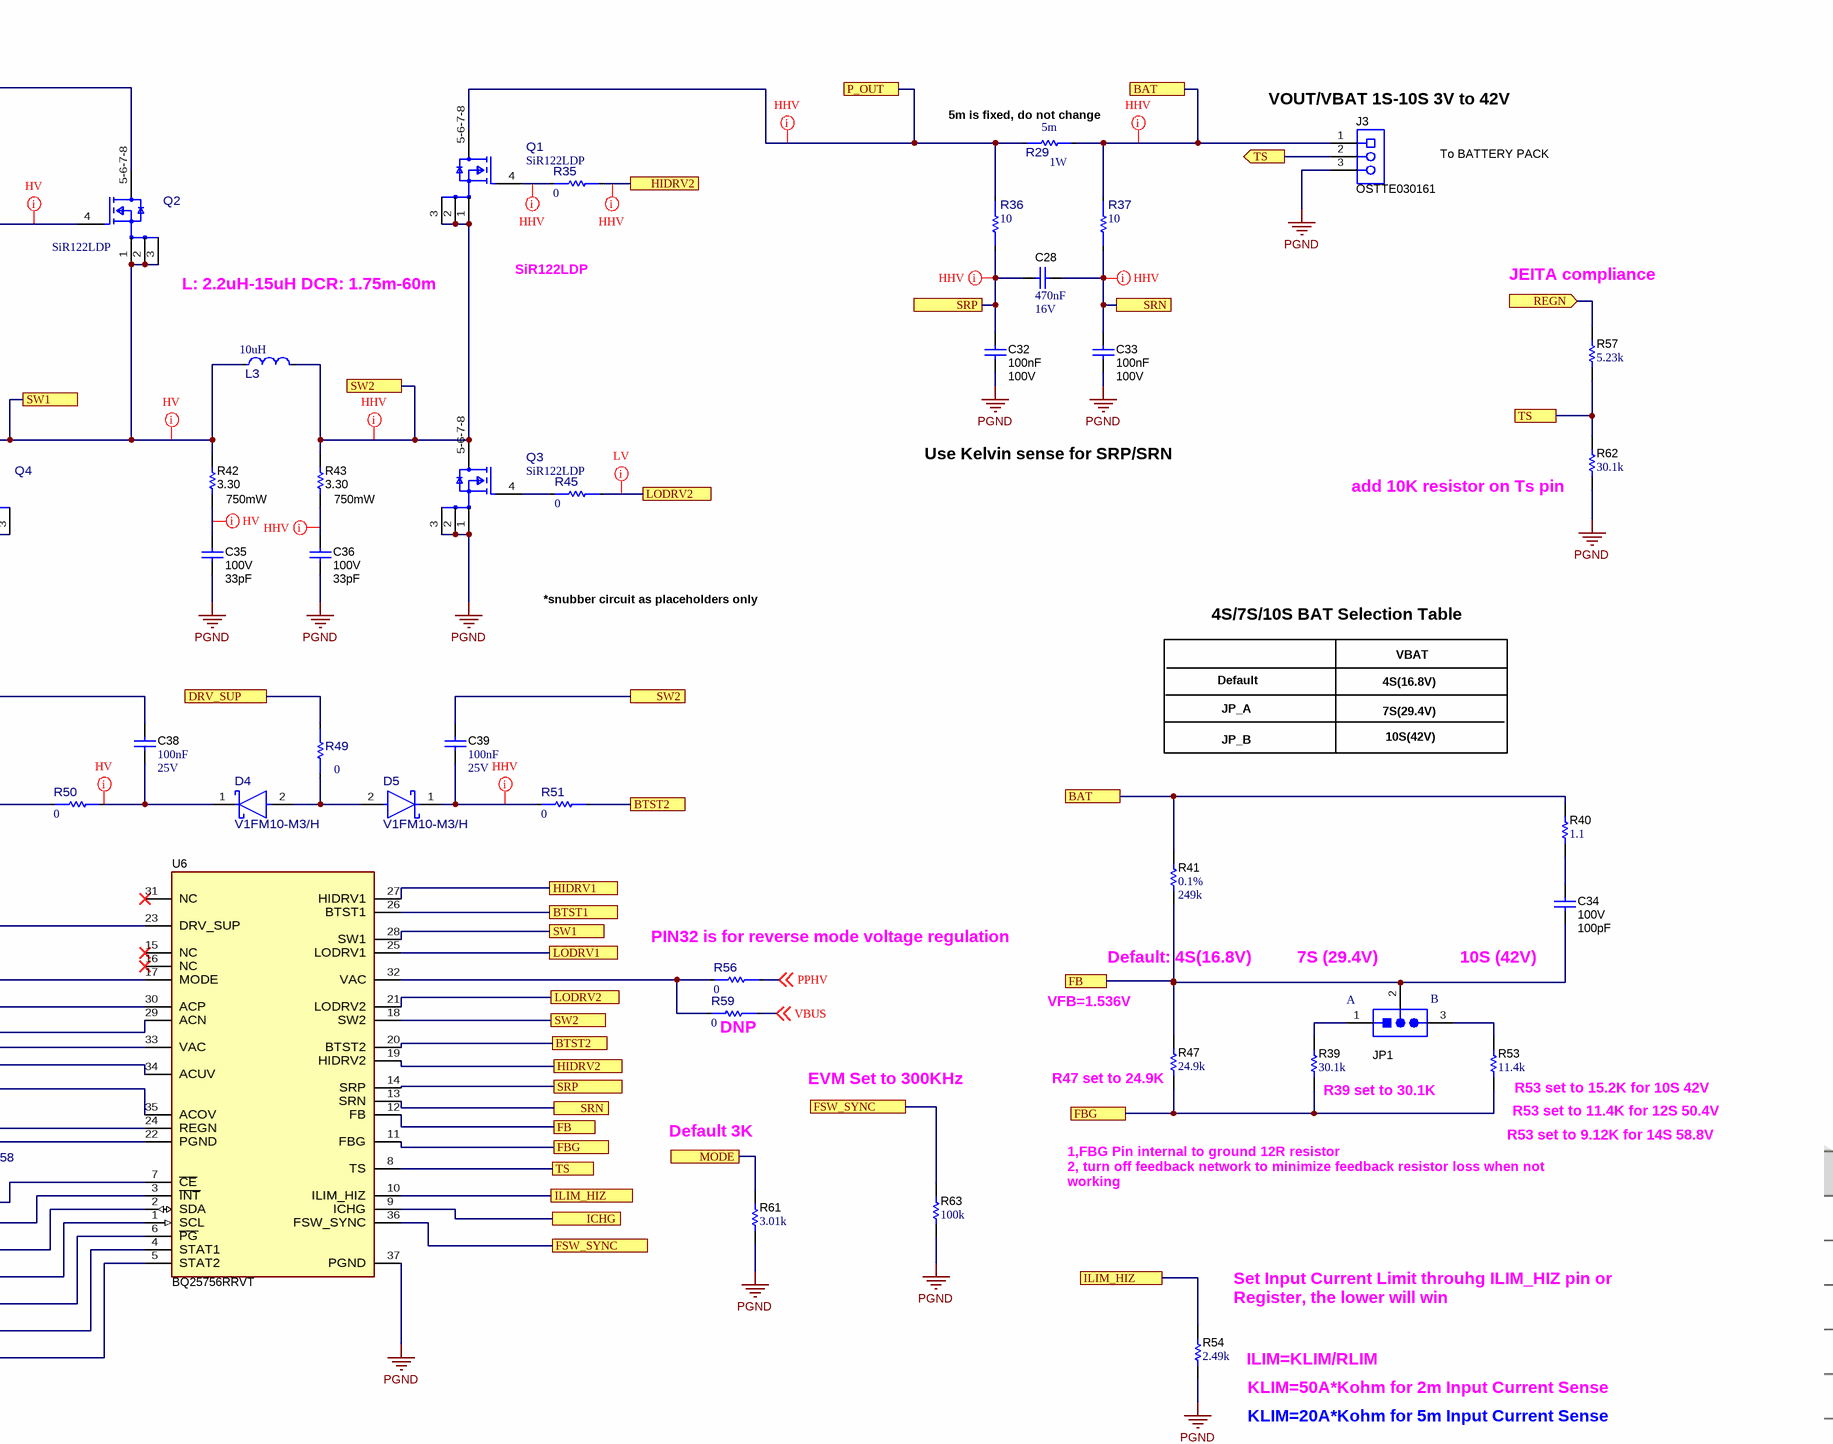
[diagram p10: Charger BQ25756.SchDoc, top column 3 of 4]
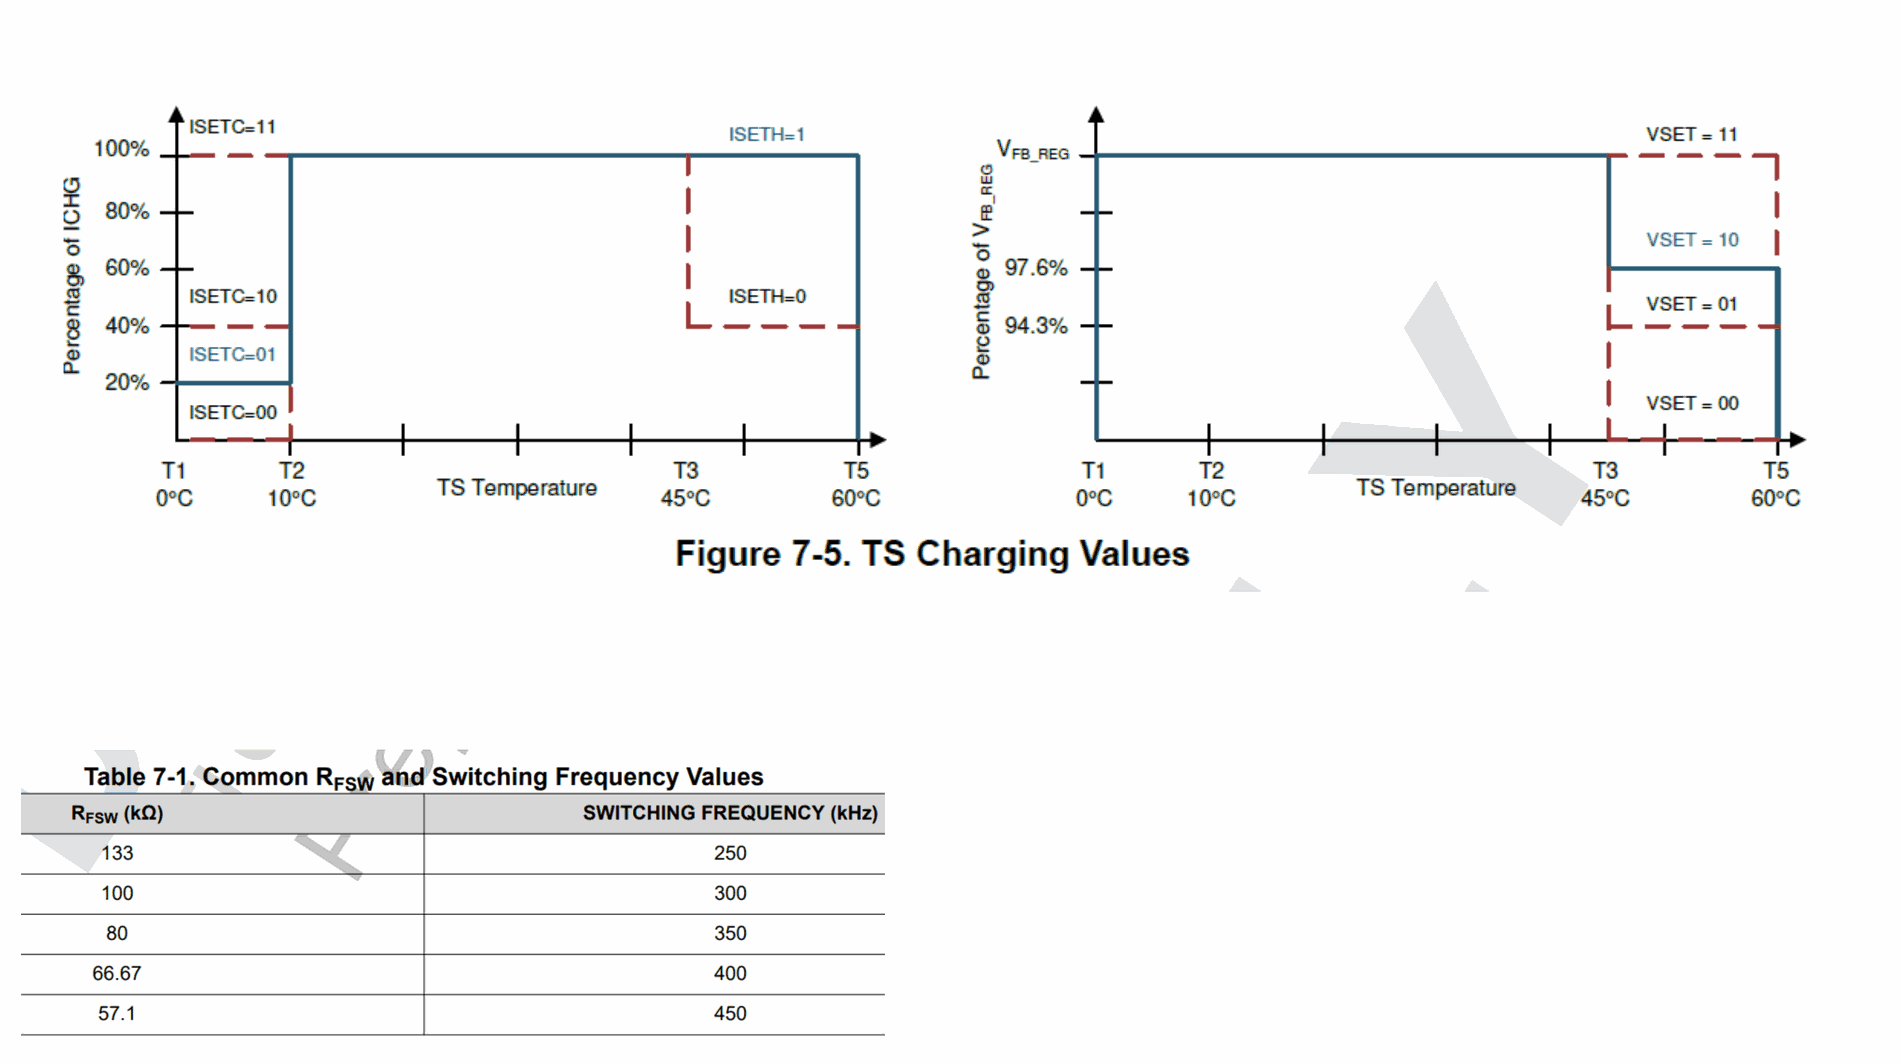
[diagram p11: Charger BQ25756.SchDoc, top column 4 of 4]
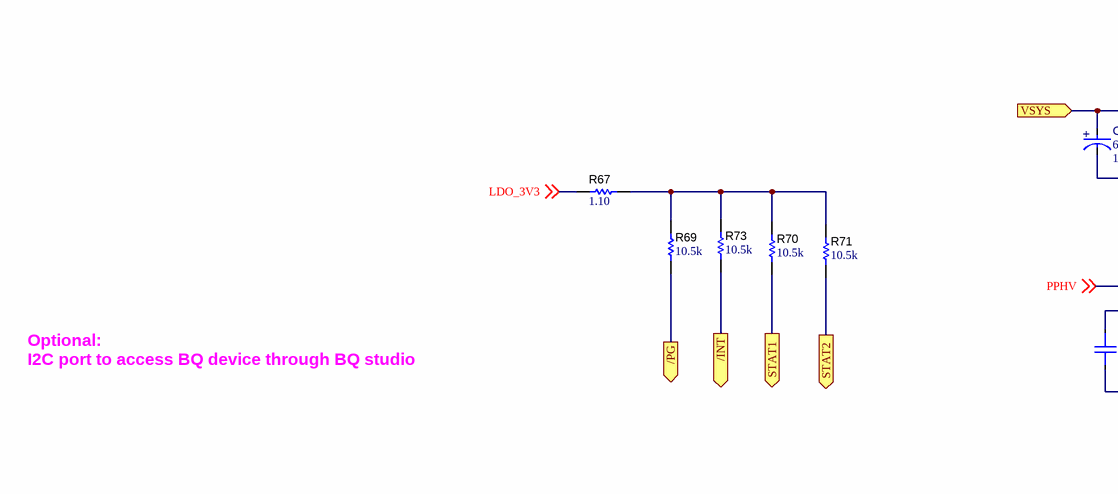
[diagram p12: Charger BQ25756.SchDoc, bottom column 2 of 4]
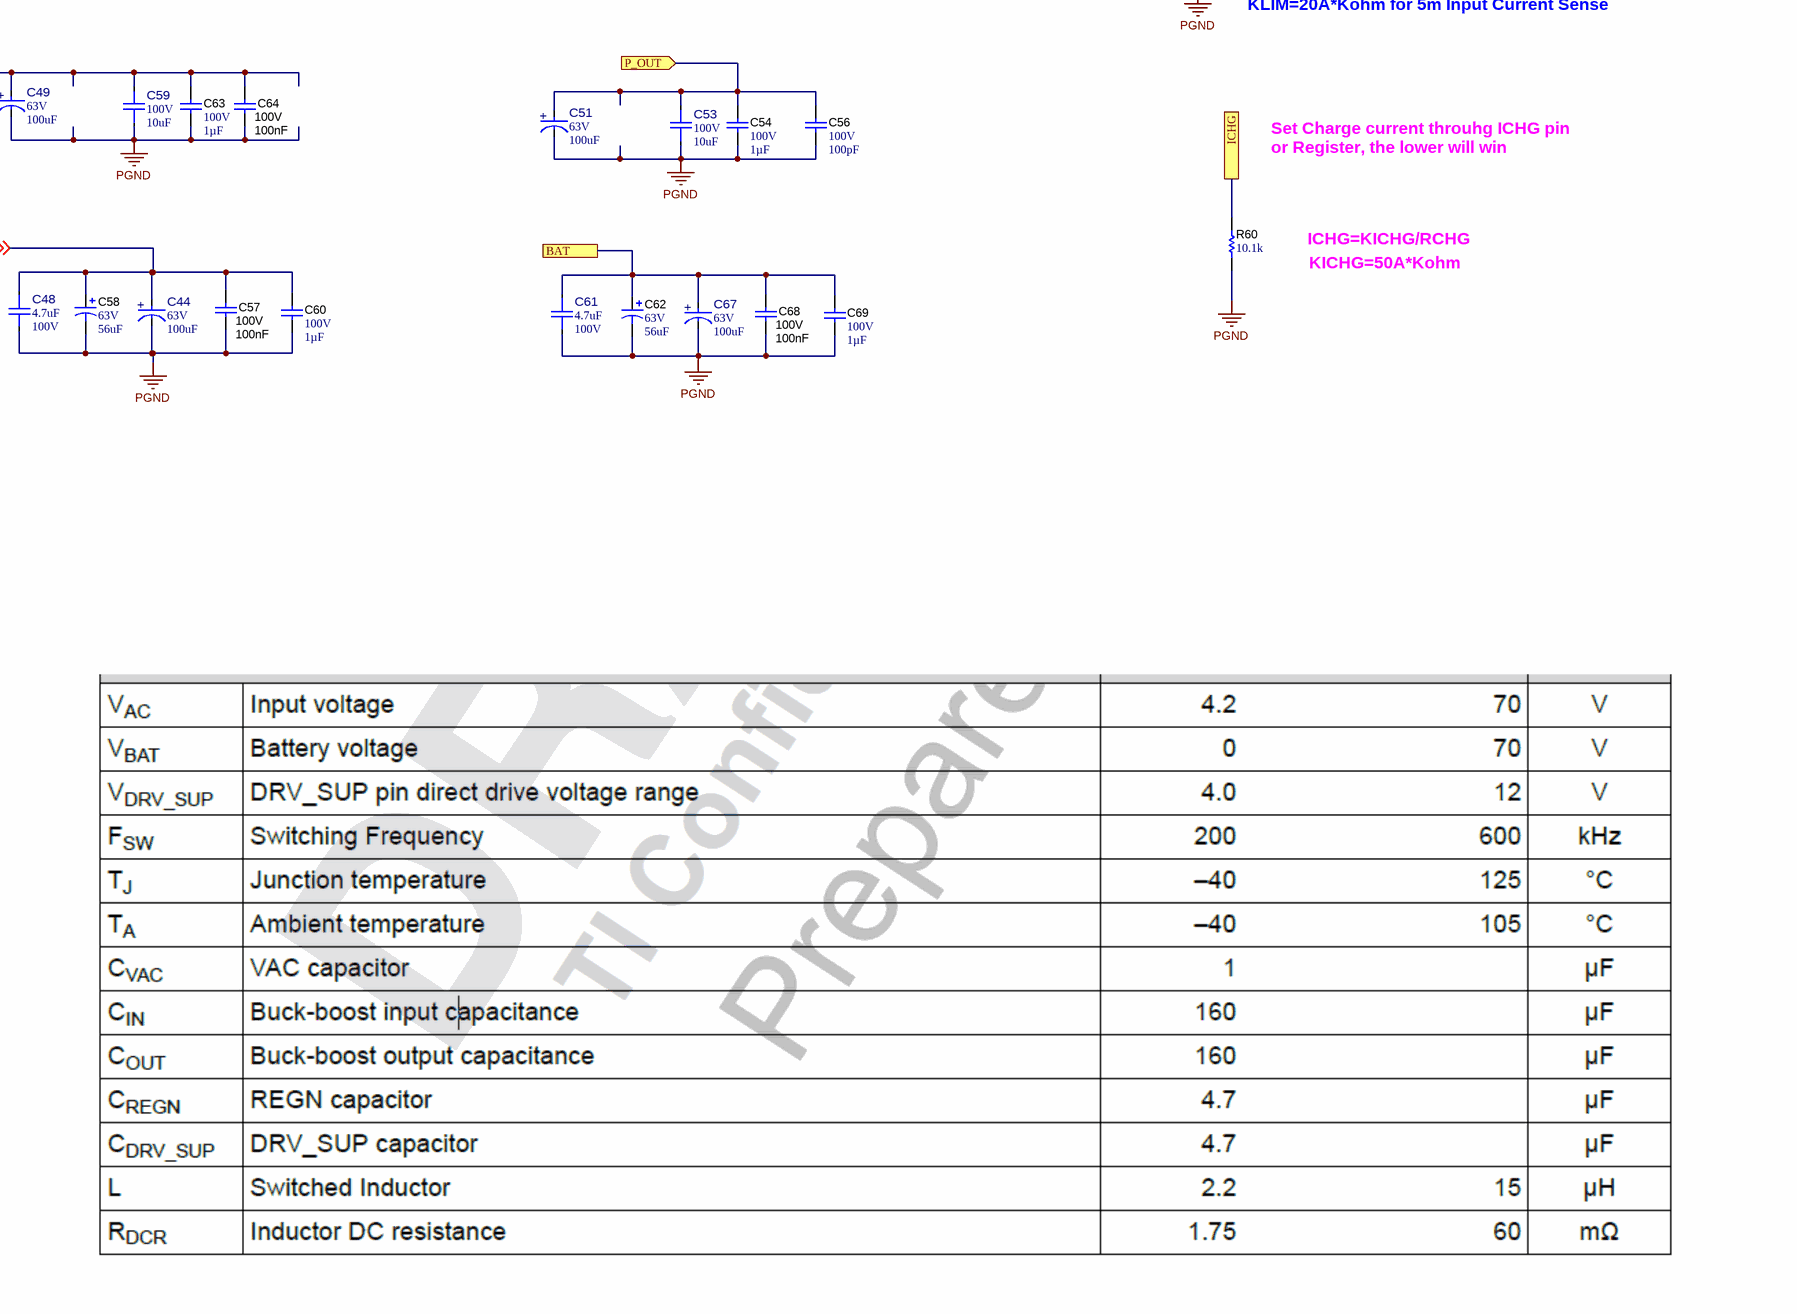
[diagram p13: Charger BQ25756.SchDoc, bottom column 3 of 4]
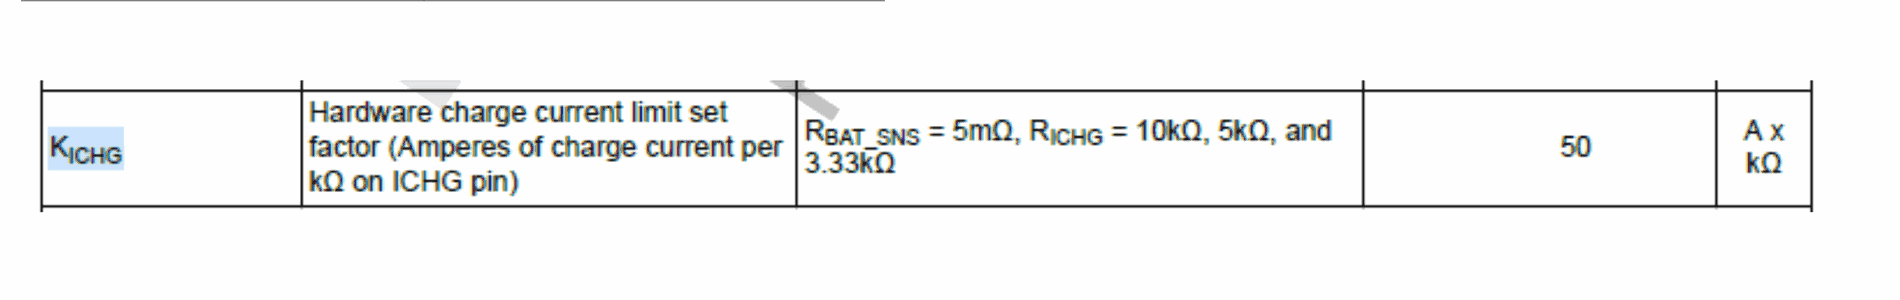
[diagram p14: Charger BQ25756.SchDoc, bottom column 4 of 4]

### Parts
C27  Cap_F: 470nF  VDC_V: 16V  [0603]  (hidden comment: C0603C474K4RACTU)
C28  Cap_F: 470nF  VDC_V: 16V  [0603]  (hidden comment: C0603C474K4RACTU)
C29  ValueDisplayed: 4.7uF  VDC_V: 100V  [FP-GCJ32DC72A475KE01L_1210-MFG]  (hidden comment: GCJ32DC72A475KE01L)
C30  Cap_F: 100nF  VDC_V: 100V  [0603_HV]  (hidden comment: HMK107B7104KAHT)
C31  Cap_F: 100nF  VDC_V: 100V  [0603_HV]  (hidden comment: HMK107B7104KAHT)
C32  Cap_F: 100nF  VDC_V: 100V  [0603_HV]  (hidden comment: HMK107B7104KAHT)
C33  Cap_F: 100nF  VDC_V: 100V  [0603_HV]  (hidden comment: HMK107B7104KAHT)
C34  VDC_V: 100V  ValueDisplayed: 100pF  [0603_HV]  (hidden comment: GCM1885C2A101JA16D)
C35  VDC_V: 100V  ValueDisplayed: 33pF  [0603_HV]  (hidden comment: 06031A330JAT2A)
C36  VDC_V: 100V  ValueDisplayed: 33pF  [0603_HV]  (hidden comment: 06031A330JAT2A)
C37  Cap_F: 100nF  VDC_V: 100V  [0603_HV]  (hidden comment: HMK107B7104KAHT)
C38  Cap_F: 100nF  VDC_V: 25V  [0603_HV]  (hidden comment: 06033C104KAT2A)
C39  Cap_F: 100nF  VDC_V: 25V  [0603_HV]  (hidden comment: 06033C104KAT2A)
C40  Cap_F: 100nF  VDC_V: 100V  [0603_HV]  (hidden comment: HMK107B7104KAHT)
C41  VDC_V: 100V  Cap_F: 1µF  [0805_150]  (hidden comment: 08051C105K4Z2A)
C42  VDC_V: 25V  Cap_F: 4.7µF  [FP-CGA4J1X7R1E475K125AE_0805-MFG]  (hidden comment: CGA4J1X7R1E475K125AE)
C43  Cap_F: 100nF  [0603_HV]  (hidden comment: HMK107B7104KAHT)
C44  VDC_V: 63V  ValueDisplayed: 100uF  [FP-PCR1J101MCL1GS_SMD_RADIAL-MFG]  (hidden comment: PCR1J101MCL1GS)
C47  VDC_V: 25V  Cap_F: 4.7µF  [FP-CGA4J1X7R1E475K125AE_0805-MFG]  (hidden comment: CGA4J1X7R1E475K125AE)
C48  ValueDisplayed: 4.7uF  VDC_V: 100V  [FP-GCJ32DC72A475KE01L_1210-MFG]  (hidden comment: GCJ32DC72A475KE01L)
C49  VDC_V: 63V  ValueDisplayed: 100uF  [FP-PCR1J101MCL1GS_SMD_RADIAL-MFG]  (hidden comment: PCR1J101MCL1GS)
C51  VDC_V: 63V  ValueDisplayed: 100uF  [FP-PCR1J101MCL1GS_SMD_RADIAL-MFG]  (hidden comment: PCR1J101MCL1GS)
C53  VDC_V: 100V  ValueDisplayed: 10uF  [FP-C3225X7R2A106K250AC_1210-MFG]  (hidden comment: C3225X7R2A106K250AC)
C54  VDC_V: 100V  Cap_F: 1µF  [0805_150]  (hidden comment: 08051C105K4Z2A)
C56  VDC_V: 100V  ValueDisplayed: 100pF  [0603]  (hidden comment: CGA3E2C0G2A101J080AA)
C57  Cap_F: 100nF  VDC_V: 100V  [0603L]  (hidden comment: HMK107B7104KAHT)
C58  VDC_V: 63V  ValueDisplayed: 56uF  [SM_RADIAL_10BMM]  (hidden comment: EEHZC1J560P)
C59  VDC_V: 100V  ValueDisplayed: 10uF  [FP-C3225X7R2A106K250AC_1210-MFG]  (hidden comment: C3225X7R2A106K250AC)
C60  VDC_V: 100V  Cap_F: 1µF  [0805_150]  (hidden comment: 08051C105K4Z2A)
C61  ValueDisplayed: 4.7uF  VDC_V: 100V  [FP-GCJ32DC72A475KE01L_1210-MFG]  (hidden comment: GCJ32DC72A475KE01L)
C62  VDC_V: 63V  ValueDisplayed: 56uF  [SM_RADIAL_10BMM]  (hidden comment: EEHZC1J560P)
C63  VDC_V: 100V  Cap_F: 1µF  [0805_150]  (hidden comment: 08051C105K4Z2A)
C64  Cap_F: 100nF  VDC_V: 100V  [0603L]  (hidden comment: HMK107B7104KAHT)
C67  VDC_V: 63V  ValueDisplayed: 100uF  [FP-PCR1J101MCL1GS_SMD_RADIAL-MFG]  (hidden comment: PCR1J101MCL1GS)
C68  Cap_F: 100nF  VDC_V: 100V  [0603L]  (hidden comment: HMK107B7104KAHT)
C69  VDC_V: 100V  Cap_F: 1µF  [0805_150]  (hidden comment: 08051C105K4Z2A)
D4  V1FM10-M3/H  [FP-V1FM10-M3-H_DO-219AB-MFG]
D5  V1FM10-M3/H  [FP-V1FM10-M3-H_DO-219AB-MFG]
J3  OSTTE030161  [On-Shore_OSTTE030161]
J4  90120-0122  [CONN_90120-0122]
JP1  PEC03SAAN  [CONN_PEC03SAAN]  (value not drawn)
L3  value 10uH  [FP-CMLB135T-100MS_SMT2_13MM45_12Mm6-MFG]  (hidden comment: CMLB135T-100MS)
Q1  Value2: SiR122LDP  [FP-SIR880BDP-T1-RE3_SO-8-MFG]  (hidden comment: SIR880BDP-T1-RE3)
Q2  Value2: SiR122LDP  [FP-SIR880BDP-T1-RE3_SO-8-MFG]  (hidden comment: SIR880BDP-T1-RE3)
Q3  Value2: SiR122LDP  [FP-SIR880BDP-T1-RE3_SO-8-MFG]  (hidden comment: SIR880BDP-T1-RE3)
Q4  Value2: SiR122LDP  [FP-SIR880BDP-T1-RE3_SO-8-MFG]  (hidden comment: SIR880BDP-T1-RE3)
R16  value 0  [FP-CRCW06031R50FKEAHP_0603-MFG]  (hidden comment: CRCW06030000Z0EA)
R29  Res_ohm: 5m  Power_W: 1W  [FP-WSL25125L000FEA_2512-MFG]  (hidden comment: WSL25125L000FEA)
R31  Res_ohm: 5m  Power_W: 1W  [FP-WSL25125L000FEA_2512-MFG]  (hidden comment: WSL25125L000FEA)
R33  value 10  [FP-CRCW060310R0FKEB_0603-MFG]  (hidden comment: CRCW060310R0FKEB)
R34  value 10  [FP-CRCW060310R0FKEB_0603-MFG]  (hidden comment: CRCW060310R0FKEB)
R35  value 0  [FP-CRCW06031R50FKEAHP_0603-MFG]  (hidden comment: CRCW06030000Z0EA)
R36  value 10  [FP-CRCW060310R0FKEB_0603-MFG]  (hidden comment: CRCW060310R0FKEB)
R37  value 10  [FP-CRCW060310R0FKEB_0603-MFG]  (hidden comment: CRCW060310R0FKEB)
R38  value 0  [FP-CRCW06031R50FKEAHP_0603-MFG]  (hidden comment: CRCW06030000Z0EA)
R39  ValueDisplayed: 30.1k  [0603]  (hidden comment: RT0603BRD0730K1L)
R40  ValueDisplayed: 1.1  [0603]  (hidden comment: CRCW06031R10JNEA)
R41  Value1: 0.1%  ValueDisplayed: 249k  [0805_HV]  (hidden comment: ERJ-PB6B2493V)
R42  Power_W: 750mW  ValueDisplayed: 3.30  [1210]  (hidden comment: CRCW12103R30FKEAHP)
R43  Power_W: 750mW  ValueDisplayed: 3.30  [1210]  (hidden comment: CRCW12103R30FKEAHP)
R44  value 0  [FP-CRCW06031R50FKEAHP_0603-MFG]  (hidden comment: CRCW06030000Z0EA)
R45  value 0  [FP-CRCW06031R50FKEAHP_0603-MFG]  (hidden comment: CRCW06030000Z0EA)
R46  ValueDisplayed: 1.00M  [0805_HV]  (hidden comment: CRCW08051M00FKEAC)
R47  ValueDisplayed: 24.9k  [0603]  (hidden comment: RT0603BRD0724K9L)
R48  ValueDisplayed: 294k  [0603]  (hidden comment: RC0603FR-07294KL)
R49  value 0  [FP-CRCW080510R0JNEAHP_0805-MFG]  (hidden comment: CRCW08050000Z0EA)
R50  value 0  [FP-CRCW06031R50FKEAHP_0603-MFG]  (hidden comment: CRCW06030000Z0EA)
R51  value 0  [FP-CRCW06031R50FKEAHP_0603-MFG]  (hidden comment: CRCW06030000Z0EA)
R52  ValueDisplayed: 64.9k  [0603]  (hidden comment: RC0603FR-0764K9L)
R53  ValueDisplayed: 11.4k  [0603]  (hidden comment: RT0603BRD0711K4L)
R54  ValueDisplayed: 2.49k  [0603]  (hidden comment: RC0603FR-072K49L)
R55  value 0  [FP-CRCW06031R50FKEAHP_0603-MFG]  (hidden comment: CRCW06030000Z0EA)
R56  value 0  [FP-CRCW06031R50FKEAHP_0603-MFG]  (hidden comment: CRCW06030000Z0EA)
R57  ValueDisplayed: 5.23k  [0603]  (hidden comment: RC0603FR-075K23L)
R58  value 0  [FP-CRCW06031R50FKEAHP_0603-MFG]  (hidden comment: CRCW06030000Z0EA)
R59  value 0  [FP-CRCW06031R50FKEAHP_0603-MFG]  (hidden comment: CRCW06030000Z0EA)
R60  ValueDisplayed: 10.1k  [0603]  (hidden comment: M55342E12B10B1T)
R61  ValueDisplayed: 3.01k  [0603]  (hidden comment: CRCW06033K01FKEA)
R62  ValueDisplayed: 30.1k  [0603]  (hidden comment: RC0603FR-0730K1L)
R63  ValueDisplayed: 100k  [0603]  (hidden comment: RC0603FR-07100KL)
R64  value 0  [FP-CRCW080510R0JNEAHP_0805-MFG]  (hidden comment: CRCW08050000Z0EA)
R67  ValueDisplayed: 1.10  [0402]  (hidden comment: CRCW04021R10FKED)
R68  value 0  [FP-CRCW080510R0JNEAHP_0805-MFG]  (hidden comment: CRCW08050000Z0EA)
R69  ValueDisplayed: 10.5k  [0402]  (hidden comment: RC0402FR-0710K5L)
R70  ValueDisplayed: 10.5k  [0402]  (hidden comment: RC0402FR-0710K5L)
R71  ValueDisplayed: 10.5k  [0402]  (hidden comment: RC0402FR-0710K5L)
R72  value 0  [FP-CRCW06031R50FKEAHP_0603-MFG]  (hidden comment: CRCW06030000Z0EA)
R73  ValueDisplayed: 10.5k  [0402]  (hidden comment: RC0402FR-0710K5L)
U6  BQ25756RRVT  [RRV0036A-MFG]

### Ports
/CE, /INT, /INT (out), /PG, /PG (out), ACN, ACOV, ACP, ACUV, BAT, BTST1, BTST2, DRV_SUP, EXT_DRV, FB, FBG, FSW_SYNC, HIDRV1, HIDRV2, ICHG, ILIM_HIZ, LODRV1, LODRV2, MODE, P_OUT, P_OUT (in), REGN, REGN (in), SRN, SRP, STAT1, STAT1 (out), STAT2, STAT2 (out), SW1, SW2, TS, TS (out), VSYS, VSYS (in)

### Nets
PGND: C29.1 C30.2 C31.2 C32.2 C33.2 C35.2 C36.2 C37.2 C40.2 C41.2 C42.2 C43.1 C44.1(CATHODE) C47.2 C48.2 C49.1(CATHODE) C51.1(CATHODE) C53.1 C54.2 C56.2 C57.2 C58.2(-) C59.1 C60.2 C61.2 C62.2(-) C63.2 C64.2 C67.1(CATHODE) C68.2 C69.2 J3.3 J4.2 Q3.1(S) Q3.2(S) Q3.3(S) Q4.1(S) Q4.2(S) Q4.3(S) R52.1 R54.1 R58.2 R60.1 R61.1 R62.1 R63.1 U6.22(PGND) U6.37(PGND)
/CE: R58.1 U6.7(~{CE}) ; port /CE
/INT: R73.1 U6.3(~{INT}) ; port /INT
/PG: R69.1 U6.6(~{PG}) ; port /PG
ACN: C27.2 C31.1 R34.1 U6.29(ACN) ; port ACN
ACOV: C40.1 R48.1 R52.2 U6.35(ACOV) ; port ACOV
ACP: C27.1 C30.1 R33.1 U6.30(ACP) ; port ACP
ACUV: C37.1 R46.1 R48.2 U6.34(ACUV) ; port ACUV
BAT: C61.1 C62.1(+) C67.2(ANODE) C68.1 C69.1 J3.1 R29.2 R37.1 R40.2 R41.2 ; port BAT
BTST1: R50.1 U6.26(BTST1) ; port BTST1
BTST2: R51.1 U6.20(BTST2) ; port BTST2
DRV_SUP: C42.1 R16.1 R49.2 R55.2 R72.2 U6.23(DRV_SUP) ; port DRV_SUP
EXT_DRV: J4.1 R16.2 ; port EXT_DRV
FB: C34.2 JP1.2 R41.1 R47.2 U6.12(FB) ; port FB
FBG: R39.1 R47.1 R53.1 U6.11(FBG) ; port FBG
FSW_SYNC: R63.2 U6.36(FSW_SYNC) ; port FSW_SYNC
HIDRV1: R38.2 U6.27(HIDRV1) ; port HIDRV1
HIDRV2: R35.2 U6.19(HIDRV2) ; port HIDRV2
I2C_SCL: R68.2 ; off-sheet I2C_SCL
I2C_SDA: R64.2 ; off-sheet I2C_SDA
ICHG: R60.2 U6.9(ICHG) ; port ICHG
ILIM_HIZ: R54.2 U6.10(ILIM_HIZ) ; port ILIM_HIZ
LDO_3V3: R67.1 ; off-sheet LDO_3V3
LODRV1: R44.1 U6.25(LODRV1) ; port LODRV1
LODRV2: R45.1 U6.21(LODRV2) ; port LODRV2
MODE: R61.2 U6.17(MODE) ; port MODE
P5V0: R72.1 ; off-sheet P5V0
P_OUT: C51.2(ANODE) C53.2 C54.1 C56.1 Q1.5-6-7-8(D) R29.1 R36.1 ; port P_OUT
PPHV: C29.2 C41.1 C43.2 C44.2(ANODE) C48.1 C57.1 C58.1(+) C60.1 R31.1 R33.2 R46.2 R56.1 U6.33(VAC) ; off-sheet PPHV
REGN: C47.1 R55.1 R57.2 U6.24(REGN) ; port REGN
SRN: C28.2 C33.1 R37.2 U6.13(SRN) ; port SRN
SRP: C28.1 C32.1 R36.2 U6.14(SRP) ; port SRP
STAT1: R70.1 U6.4(STAT1) ; port STAT1
STAT2: R71.1 U6.5(STAT2) ; port STAT2
SW1: C38.1 L3.1 Q2.1(S) Q2.2(S) Q2.3(S) Q4.5-6-7-8(D) R42.2 U6.28(SW1) ; port SW1
SW2: C39.2 L3.2 Q1.1(S) Q1.2(S) Q1.3(S) Q3.5-6-7-8(D) R43.2 U6.18(SW2) ; port SW2
TS: J3.2 R57.1 R62.2 U6.8(TS) ; port TS
VBUS: R59.1 ; off-sheet VBUS
VSYS: C49.2(ANODE) C59.2 C63.1 C64.1 Q2.5-6-7-8(D) R31.2 R34.2 ; port VSYS
NetC34_1: C34.1 R40.1
NetC35_1: C35.1 R42.1
NetC36_1: C36.1 R43.1
NetC38_2: C38.2 D4.1(CATHODE) R50.2
NetC39_1: C39.1 D5.1(CATHODE) R51.2
NetD4_2: D4.2(ANODE) D5.2(ANODE) R49.1
NetJP1_1: JP1.1 R39.2
NetJP1_3: JP1.3 R53.2
NetQ1_4: Q1.4(G) R35.1
NetQ2_4: Q2.4(G) R38.1
NetQ3_4: Q3.4(G) R45.2
NetQ4_4: Q4.4(G) R44.2
NetR56_2: R56.2 R59.2 U6.32(VAC)
NetR64_1: R64.1 U6.2(SDA)
NetR67_2: R67.2 R69.2 R70.2 R71.2 R73.2
NetR68_1: R68.1 U6.1(SCL)

Not connected (* = marked no-connect by the designer): U6 15(NC)* 16(NC)* 31(NC)*

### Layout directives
net class HV: ACN, ACP, ACUV, HIDRV1, NetC35_1, NetC38_2, NetQ2_4, SW1, VSYS
net class HHV: BAT, HIDRV2, NetC36_1, NetC39_1, NetQ1_4, P_OUT, SRN, SRP, SW2
net class LV: LODRV1, LODRV2, PGND

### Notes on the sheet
- From USB Port: 5-20V
- (near R31) 2m default, higher Resister for better regulation
- (near R29) 5m is fixed, do not change
- (near J3) VOUT/VBAT 1S-10S 3V to 42V
- To BATTERY PACK
- L: 2.2uH-15uH DCR: 1.75m-60m
- SiR122LDP
- JEITA compliance
- Use Kelvin sense for ACP/ACN
- Use Kelvin sense for SRP/SRN
- (near R62) add 10K resistor on Ts pin
- (near C37) ACUV=1.1V
- (near R48) UV-4.2v  OV-SET to 25
- *snubber circuit as placeholders only
- 4S/7S/10S BAT Selection Table
- VBAT
- ACOV=1.2V
- JP_A
- Default
- 4S(16.8V)
- 7S(29.4V)
- (near R52) R52 for ACOV setting
- JP_B
- 10S(42V)
- (near R72) DNP
- (near R56) PIN32 is for reverse mode voltage regulation
- Default: 4S(16.8V)
- (near JP1) 7S (29.4V)
- 10S (42V)
- DNP
- PIN33 is for Bias Pin
- (near R59) DNP
- VFB=1.536V
- (near JP1) A
- (near JP1) B
- EXT_DRV
- Default 3K
- EVM Set to 300KHz
- (near R47) R47 set to 24.9K
- (near R39) R39 set to 30.1K
- (near R53) R53 set to 9.12K for 14S 58.8V
- (near R53) R53 set to 15.2K for 10S 42V
- (near R53) R53 set to 11.4K for 12S 50.4V
- RENG comes from PPHV at Charging mode
- 1,FBG Pin internal to ground 12R resistor
  2, turn off feedback network to minimize feedback resistor loss when not working
- REGN: LDO 5V/70mA
- RENG comes from BAT at dis-Charging mode(Higher loss due to High cell)
- (near R54) Set Input Current Limit throuhg ILIM_HIZ pin or Register, the lower will win
- EXT-DRV supply is needed if high driver loss and associated generated loss from REGN path
- ILIM=KLIM/RLIM
- KLIM=50A*Kohm for 2m Input Current Sense
- KLIM=20A*Kohm for 5m Input Current Sense
- Set Charge current throuhg ICHG pin or Register, the lower will win
- KICHG=50A*Kohm
- ICHG=KICHG/RCHG
- Optional:
  I2C port to access BQ device through BQ studio

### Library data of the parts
C27 C28 = CMP-0006944-4: CAP, CERM, 0.47 uF, 16 V, +/- 10%, X7R, 0603; Manufacturer: Kemet; TaMin_C: -55°C; Polarized: N; SizeAreaWB_mm2: 4.68; Value1: Unknown; U/M: EA; Value: 0.47uF; TaMax_C: 125°C; SizeZ_mm: 1; SizeX_mm: 1.6; SizeY_mm: 0.8; SizeArea_mm2: 1.28; AEC Category: Q200
C29 C48 C61 = CMP-0093675-1: 4.7uF ±10% 100V Ceramic Capacitor X7S 1210 (3225 Metric); Manufacturer: Murata; Value: 4.7µF; AEC Qualified: Yes; TempCo: 22%; SizeZ_mm: 2.3mm; AEC Grade: Grade 1
C30-C33 C37 C40 C57 C64 C68 = CMP-0081011-1: CAP, CERM, 0.1 µF, 100 V,+/- 10%, X7R, AEC-Q200 Grade 1, 0603; Manufacturer: Taiyo Yuden; SizeAreaWB_mm2: 4.68; SizeArea_mm2: 1.28; AEC Qualified: Y; AEC Category: Q200; Value: 0.1uF; TaMax_C: 125°C; SizeZ_mm: 1; Polarized: N; TaMin_C: -55°C; SizeY_mm: 0.8; U/M: EA; SizeX_mm: 1.6; Cap_Case: 0603; ValueDisplayed: 0.1µF
C34 = CMP-0007130-4: CAP, CERM, 100 pF, 100 V, +/- 5%, C0G/NP0, AEC-Q200 Grade 1, 0603; Manufacturer: MuRata; TaMin_C: -55°C; Polarized: N; SizeAreaWB_mm2: 4.68; Value1: Unknown; U/M: EA; TaMax_C: 125°C; SizeZ_mm: 1; SizeX_mm: 1.6; SizeY_mm: 0.8; Cap_Case: 0603; SizeArea_mm2: 1.28; AEC Qualified: Y; AEC Category: Q200; Value: 100pF
C35 C36 = CMP-0006722-4: CAP, CERM, 33 pF, 100 V, +/- 5%, C0G/NP0, 0603; Manufacturer: AVX; TaMin_C: -55°C; ESR_ohm: 0.209; Polarized: N; SizeAreaWB_mm2: 4.68; Value1: 0.209 ohm; U/M: EA; Value: 33pF; TaMax_C: 125°C; SizeZ_mm: 1; SizeX_mm: 1.6; SizeY_mm: 0.8; Cap_Case: 0603; SizeArea_mm2: 1.28; AEC Category: Q200
C38 C39 = CMP-0006753-4: CAP, CERM, 0.1 uF, 25 V, +/- 10%, X7R, 0603; Manufacturer: AVX; TaMin_C: -55°C; ESR_ohm: 50m; Polarized: N; SizeAreaWB_mm2: 4.68; Value1: 0.05 ohm; U/M: EA; Value: 0.1uF; TaMax_C: 125°C; SizeZ_mm: 1; SizeX_mm: 1.6; SizeY_mm: 0.8; Cap_Case: 0603; SizeArea_mm2: 1.28; AEC Category: Q200
C41 C54 C60 C63 C69 = CMP-0861070-1: CAP, CERM, 1 µF, 100 V,+/- 10%, X7R, AEC-Q200 Grade 1, 0805; Manufacturer: AVX; SizeZ_mm: 1.5; Polarized: N; TaMax_C: 125°C; TaMin_C: -55°C; Value: 1uF; AEC Qualified: Y; U/M: EA; AEC Grade: 1; Cap_Case: 0805; SizeX_mm: 2; SizeArea_mm2: 2.5; SizeAreaWB_mm2: 6.75; AEC Category: Q200; SizeY_mm: 1.25
C42 C47 = CMP-0093626-1: Cap Ceramic 4.7uF 25V X7R 10% Pad SMD 0805 +125°C Automotive T/R; Manufacturer: TDK Corporation; SizeZ_mm: 1.45mm; TempCo: 15%; AEC Qualified: Yes; Value: 4.7µF; Tolerance_%: 0.1%; AEC Grade: Grade 1
C43 = CMP-0081011-1: CAP, CERM, 0.1 µF, 100 V,+/- 10%, X7R, AEC-Q200 Grade 1, 0603; Manufacturer: Taiyo Yuden; SizeAreaWB_mm2: 4.68; SizeArea_mm2: 1.28; AEC Qualified: Y; AEC Category: Q200; Value: 0.1uF; TaMax_C: 125°C; SizeZ_mm: 1; Polarized: N; TaMin_C: -55°C; VDC_V: 100V; SizeY_mm: 0.8; U/M: EA; SizeX_mm: 1.6; Cap_Case: 0603; ValueDisplayed: 0.1µF
C44 C49 C51 C67 = CMP-0089206-1: 100uF 63V Polymer ALUM Electrolytic Capacitor, CR Series 4000h 10.3x10.3x12.6mm; Manufacturer: Nichicon; Tolerance_%: 20%; AEC Grade: Grade 1; Cap_F: 100µF; IRMS_A: 3A; Life: 4000Hours; AEC Qualified: Yes; SizeZ_mm: 12.7mm; Dissipation Factor: 8%; Esr: 24m; Leakage Current: 189uA
C53 C59 = CMP-0096021-1: 10 µF ±10% 100V Ceramic Capacitor X7R 1210 (3225 Metric); Manufacturer: TDK; Cap_F: 10µF; AEC Qualified: No; Value: 10µF; SizeZ_mm: 2.85mm; TempCo: 15%
C56 = CMP-0007237-3: Multilayer Ceramic Capacitors MLCC - SMD/SMT CGA 0603 100V 100pF C0G 5% AEC-Q200; Manufacturer: TDK; TaMin_C: -55°C; Polarized: N; TempCo: C0G/NP0; SizeAreaWB_mm2: 4.68; Value1: Unknown; U/M: EA; TaMax_C: 125°C; SizeZ_mm: 1; SizeX_mm: 1.6; SizeY_mm: 0.8; SizeArea_mm2: 1.28; AEC Category: Q200
C58 C62 = CMP-0012603-3: CAP, Polymer Hybrid, 56 uF, 63 V, +/- 20%, 30 ohm, 10x10 SMD; Manufacturer: Panasonic; TaMin_C: -55°C; ESR_ohm: 30; Polarized: Y; SizeAreaWB_mm2: 159.9; Value1: 30 ohm; Value: 56uF; TaMax_C: 125°C; SizeZ_mm: 10.2; SizeX_mm: 11; SizeY_mm: 10.3; SizeArea_mm2: 113.3; CompType: Capacitor; Cap_F: 56µF; IRMS_A: 1.4A; AEC Category: Q200
D4 D5 = CMP-0093639-2: Diode Schottky 1A Surface Mount DO-219AB (SMF); Manufacturer: Vishay; Max Surge Forward Current: 30A; TJmax_C: 175°C; AEC Qualified: No; Cap_F: 95pF; AEC Category: Q101; Standoff Height: 0mm; SizeZ_mm: 1.08mm; Vr_V: 100V; Peak Reverse Current: 0.2uA
J3 = CMP-0075352-1: Terminal Block, 3.5mm, 3x1, Tin, R/A, TH; Manufacturer: On-Shore Technology; CNHeader: False; Current_A: 10A; Green_Lifecycle: Not Set; Gender: Female; Cert_CSA: Y; Green_REACh: Incomplete; Voltage_V: 125V; Row_Count: 1; Pitch_mm: 3.5; CT: True
J4 = CMP-0055312-1: Header, 100mil, 2x1, Tin, TH; Manufacturer: Molex; CNHeader: TRUE; Green_Lifecycle: Active; Green_REACh: Passed; CT: FALSE
JP1 = CMP-0002338-1: Header, 100mil, 3x1, Tin, TH; Manufacturer: Sullins Connector Solutions; Cert_UL: Y; CNHeader: TRUE; CT: FALSE; Current_A: 3A; Gender: Male; Green_Lifecycle: Not Set; Green_REACh: Incomplete; Pitch_mm: 2.54; Row_Count: 1; Shrouded: N; Voltage_V: 1.8kV
L3 = CMP-0096007-1: Power Choke Coil 10uH 20% 9A 22mOhm; Manufacturer: Cyntec; Material: Metal Dust; SizeZ_mm: 5mm; Standoff Height: 0mm; Ind_H: 10µH; AEC Qualified: No; Isat: 10.5A; Test Frequency: 100kHz; DCR_ohm: 22m
Q1-Q4 = CMP-0096839-1: N-Channel 80 V 18.6A (Ta), 70.6A (Tc) 5W (Ta), 71.4W (Tc) Surface Mount PowerPAK® SO-8; Manufacturer: Vishay; QgTyp_nC: 43.5nC @ 10V; Turn On Delay Time: 12ns; Rthja Max: 20°C/W; Turn Off Delay Time: 40ns; Reverse Recovery Charge: 52nC; Typ Forward Diode Voltage: 0.74V; VdsMax_V: 1.1V; SizeZ_mm: 1.12mm; Number Of Channels: 1; Pulse Drain Current: 200A; Threshold Vgs Min: 1V; TJmax_C: +150°C; AEC Qualified: No; Transconductance: 49S; ChMode: False; Reverse Recovery Time: 38ns; Threshold Vgs Max: 2.4V; Input Capacitace At Vds: 2930pF @ 40V; Vgs_V: 20V; Drain To Source Breakdown Voltage: 80V; Rdson45_ohm: 5.3m
R16 R35 R38 R44 R45 R50 R51 R55 R56 R58 R59 R72 = CMP-0093629-1: Thick Film Resistors - SMD 1/10watt ZEROohm Jumper; Manufacturer: Vishay; AEC Grade: Grade 0; TempCo: 100ppm/°C; Power: 250mW; Res_ohm: 1.5; Power_W: 330mW; AEC Qualified: Yes; VDC_V: 75V; SizeZ_mm: 0.55mm; Tolerance_%: 1%
R29 R31 = CMP-0096841-1: Res Metal Strip 2512 0.005 Ohm 1% 1W 110ppm/C Molded SMD SMD Embossed Plastic T/R; Manufacturer: Vishay; TempCo: 110ppm/°C; AEC Grade: Grade 0; AEC Qualified: Yes; Category 5A00970A6D5C81C7: Uncategorized; Value: 5m; Category 5C6A91606D4187Ad: Resistors; Category Cd01000Bfc2916C6: Single Components; Category 7542B8484461Ae85: Passive Components; SizeZ_mm: 0.889mm
R33 R34 R36 R37 = CMP-0093685-1: RES Thick Film, 10Ω, 1%, 0.1W, 100ppm/°C, 0603; Manufacturer: Vishay; Approved Alternate Part Number: 541-1.00HHCT-ND; Power_W: 100mW; Voltage: 75V; SizeZ_mm: 0.5mm; AEC Grade: Grade 0; AEC Qualified: Yes
R39 = CMP-0024096-3: RES, 30.1 k, 0.1%, 0.1 W, 0603; Manufacturer: Yageo America; Power_W: 100mW; TempCo: 25 ppm/C; Value_Code: 30k1; U/M: EA; Value: 30.1k; EIA_Code: E192; SizeX_mm: 1.6; SizeY_mm: 0.8; SizeZ_mm: 1; Value2: 0.1W; SizeArea_mm2: 1.28; VDC_V: 75V; AEC Category: Q200
R40 = CMP-0025744-3: RES, 1.1, 5%, 0.1 W, 0603; Manufacturer: Vishay-Dale; Power_W: 100mW; TempCo: 200 ppm/C; Value_Code: 1R10; U/M: EA; Value: 1.1; EIA_Code: E24; SizeX_mm: 1.6; SizeY_mm: 0.8; SizeZ_mm: 1; Value2: 0.1W; SizeArea_mm2: 1.28; VDC_V: 75V; AEC Category: Q200
R41 = CMP-0018933-2: Thick Film Resistors - SMD 0805 Anti-Surge Res. 0.1%, 249Kohm; Manufacturer: Panasonic; Power_W: 125mW; TempCo: 25 ppm/C; U/M: EA; Value: 249k; EIA_Code: E192; SizeX_mm: 2; SizeY_mm: 1.25; SizeZ_mm: 1.45; Value2: 0.125W; SizeArea_mm2: 2.5; VDC_V: 100V; AEC Category: Q200
R42 R43 = CMP-0015022-3: RES, 3.30, 1%, 0.75 W, AEC-Q200 Grade 0, 1210; Manufacturer: Vishay-Dale; TempCo: 100 ppm/C; SizeAreaWB_mm2: 14.7; Value_Code: 3R30; Value: 3.30; Res_ohm: 3.3; SizeX_mm: 3.2; SizeY_mm: 2.5; SizeZ_mm: 1.35; Value2: 0.75W; SizeArea_mm2: 8; AEC Qualified: Y; AEC Grade: 0; AEC Category: Q200
R46 = CMP-0021522-3: Thick Film Resistors - SMD 1/8Watt 1Mohms 1% Commercial Use; Manufacturer: Vishay / Dale; Power_W: 125mW; TempCo: 100 ppm/C; Value_Code: 1M00; Value: 1.00Meg; EIA_Code: E96; Res_ohm: 1M; SizeX_mm: 2; SizeY_mm: 1.25; SizeZ_mm: 1.45; Value2: 0.125W; SizeArea_mm2: 2.5; AEC Qualified: Y; AEC Category: Q200; AEC Grade: 0; SizeAreaWB_mm2: 6.75
R47 = CMP-0023990-3: RES, 24.9 k, 0.1%, 0.1 W, 0603; Manufacturer: Yageo America; Power_W: 100mW; TempCo: 25 ppm/C; Value_Code: 24k9; U/M: EA; Value: 24.9k; EIA_Code: E192; SizeX_mm: 1.6; SizeY_mm: 0.8; SizeZ_mm: 1; Value2: 0.1W; SizeArea_mm2: 1.28; VDC_V: 75V; AEC Category: Q200
R48 = CMP-0022977-4: RES, 294 k, 1%, 0.1 W, 0603; Manufacturer: Yageo; Power_W: 100mW; TempCo: 100 ppm/C; Value: 294k; EIA_Code: E96; SizeX_mm: 1.6; SizeY_mm: 0.8; SizeZ_mm: 1; Value2: 0.1W; SizeArea_mm2: 1.28; AEC Qualified: N; VDC_V: 75V; AEC Category: Q200; SizeAreaWB_mm2: 4.68
R49 R64 R68 = CMP-0092857-1: Thick Film Resistors - SMD 1/8watt ZEROohm Jumper; Manufacturer: Vishay; Power_W: 500mW; SizeZ_mm: 0.6mm; AEC Qualified: Yes; TempCo: 200ppm/°C; VDC_V: 150V; Tolerance_%: 5%; AEC Grade: Grade 0
R52 = CMP-0023228-5: RES, 64.9 k, 1%, 0.1 W, 0603; Manufacturer: Yageo; Power_W: 100mW; TempCo: 100 ppm/C; Value_Code: 64k9; Value: 64.9k; EIA_Code: E96; SizeX_mm: 1.6; SizeY_mm: 0.8; SizeZ_mm: 1; Value2: 0.1W; SizeArea_mm2: 1.28; AEC Qualified: N; VDC_V: 75V; AEC Category: Q200; SizeAreaWB_mm2: 4.68
R53 = CMP-0023678-2: RES, 11.4 k, 0.1%, 0.1 W, 0603; Manufacturer: Yageo America; Power_W: 100mW; TempCo: 25 ppm/C; Value_Code: 11k4; U/M: EA; Value: 11.4k; EIA_Code: E192; SizeX_mm: 1.6; SizeY_mm: 0.8; SizeZ_mm: 1; Value2: 0.1W; SizeArea_mm2: 1.28; VDC_V: 75V; AEC Category: Q200
R54 = CMP-0022990-5: RES, 2.49 k, 1%, 0.1 W, 0603; Manufacturer: Yageo; Power_W: 100mW; TempCo: 100 ppm/C; Value_Code: 2k49; Value: 2.49k; EIA_Code: E96; SizeX_mm: 1.6; SizeY_mm: 0.8; SizeZ_mm: 1; Value2: 0.1W; SizeArea_mm2: 1.28; AEC Qualified: N; VDC_V: 75V; AEC Category: Q200; SizeAreaWB_mm2: 4.68
R57 = CMP-0023199-5: RES, 5.23 k, 1%, 0.1 W, 0603; Manufacturer: Yageo; Power_W: 100mW; TempCo: 100 ppm/C; Value_Code: 5k23; Value: 5.23k; EIA_Code: E96; SizeX_mm: 1.6; SizeY_mm: 0.8; SizeZ_mm: 1; Value2: 0.1W; SizeArea_mm2: 1.28; AEC Qualified: N; VDC_V: 75V; AEC Category: Q200; SizeAreaWB_mm2: 4.68
R60 = CMP-0080485-1: RES, 10.1 k, 0.1%, 0.1 W, 0603; Manufacturer: TT Electronics/IRC; Power_W: 100mW; TempCo: 25 ppm/C; SizeAreaWB_mm2: 4.68; Value_Code: 10k1; Value: 10.1k; EIA_Code: E192; SizeX_mm: 1.6; SizeY_mm: 0.8; SizeZ_mm: 1; Value2: 0.1W; SizeArea_mm2: 1.28; AEC Qualified: N; AEC Category: Q200
R61 = CMP-0022371-2: RES, 3.01 k, 1%, 0.1 W, 0603; Manufacturer: Vishay-Dale; Power_W: 100mW; TempCo: 100 ppm/C; Value_Code: 3k01; U/M: EA; Value: 3.01k; EIA_Code: E96; SizeX_mm: 1.6; SizeY_mm: 0.8; SizeZ_mm: 1; Value2: 0.1W; SizeArea_mm2: 1.28; VDC_V: 75V; AEC Category: Q200
R62 = CMP-0023018-5: RES, 30.1 k, 1%, 0.1 W, 0603; Manufacturer: Yageo; Power_W: 100mW; TempCo: 100 ppm/C; Value_Code: 30k1; Value: 30.1k; EIA_Code: E96; SizeX_mm: 1.6; SizeY_mm: 0.8; SizeZ_mm: 1; Value2: 0.1W; SizeArea_mm2: 1.28; AEC Qualified: N; VDC_V: 75V; AEC Category: Q200; SizeAreaWB_mm2: 4.68
R63 = CMP-0022735-5: RES, 100 k, 1%, 0.1 W, 0603; Manufacturer: Yageo; Power_W: 100mW; TempCo: 100 ppm/C; Value: 100k; EIA_Code: E96; SizeX_mm: 1.6; SizeY_mm: 0.8; SizeZ_mm: 1; Value2: 0.1W; SizeArea_mm2: 1.28; AEC Qualified: N; VDC_V: 75V; AEC Category: Q200; SizeAreaWB_mm2: 4.68
R67 = CMP-0026133-2: RES, 1.10, 1%, 0.063 W, AEC-Q200 Grade 0, 0402; Manufacturer: Vishay-Dale; Power_W: 63mW; TempCo: 100 ppm/C; Value_Code: 1R10; Value: 1.10; EIA_Code: E96; Res_ohm: 1.1; SizeX_mm: 1; SizeY_mm: 0.5; SizeZ_mm: 0.6; Value2: 0.063W; AEC Qualified: Y; VDC_V: 50V; AEC Category: Q200; AEC Grade: 0
R69-R71 R73 = CMP-0078781-1: RES, 10.5 k, 1%, 0.063 W, 0402; Manufacturer: Yageo America; Value_Code: 10k5; SizeArea_mm2: 0.5; AEC Qualified: N; AEC Category: Q200; Value: 10.5k; SizeZ_mm: 0.6; EIA_Code: E96; TempCo: 100 ppm/C; Power_W: 63mW; VDC_V: 50V; Value2: 0.063W; SizeX_mm: 1
U6 = CMP-0093460-1: Manufacturer: Texas Instruments; Alternate Manufacturer: None; AEC Qualified: No; Standoff Height: 0mm; SizeZ_mm: 1mm

## Sheet 100W USB Type C Charger_Hardware.SchDoc
size A2; Date: Not shown in title block; ApprovedBy: Not shown in title block; CheckedBy: Not shown in title block; Author: Not shown in title block; CompanyName: Not shown in title block; Engineer: Not shown in title block; Organization: Not shown in title block; Address1: Not shown in title block; Address2: Not shown in title block; Address3: Not shown in title block; Address4: Not shown in title block; DocumentNumber: 1; Revision: Use project parameter SCH_Rev; SheetNumber: 4; SheetTotal: 4; PageSetup: Record=PageOptions¦CenterHorizontal=True¦CenterVertical=True¦PrintScale=1.00¦XCorrection=1.00¦YCorrection=1.00¦PrintKind=0¦BorderSize=5000000¦LeftOffset=0¦BottomOffset=0¦Orientation=2¦PaperLength=1000¦PaperWidth=1000¦Scale=100¦PaperSource=15¦PrintQuality=600¦MediaType=1¦DitherType=10¦PaperKind=Letter¦PrintScaleMode=1
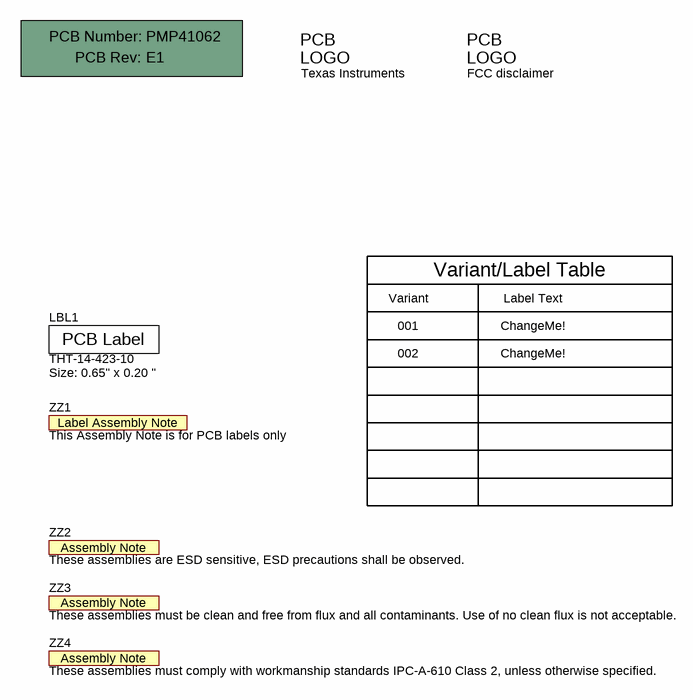
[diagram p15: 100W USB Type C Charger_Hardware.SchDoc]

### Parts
!PCB  Printed Circuit Board  (value not drawn)  (mechanical)
LBL1  THT-14-423-10  Note: Size: 0.65" x 0.20 "  [Label_650x200]
Logo1  Texas Instruments  [TI_Stacked_Overlay_Small]  (no BOM)
Logo3  FCC disclaimer  [FCC_disclaimer]  (no BOM)
ZZ1  This Assembly Note is for PCB labels only  [AssemblyNoteLabel]  (no BOM)
ZZ2  These assemblies are ESD sensitive, ESD precautions shall be observed.  [AssemblyNote]  (no BOM)
ZZ3  These assemblies must be clean and free from flux and all contaminants. Use of no clean flux is not acceptable.  [AssemblyNote]  (no BOM)
ZZ4  These assemblies must comply with workmanship standards IPC-A-610 Class 2, unless otherwise specified.  [AssemblyNote]  (no BOM)

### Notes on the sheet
- Variant
- Variant/Label Table
- Label Text
- 001
- 002
- ChangeMe!

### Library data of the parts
!PCB = CMP-0003618-2: Manufacturer: Any; PartNumber: PMP41062
LBL1 = CMP-0003625-1: Thermal Transfer Printable Labels, 0.650" W x 0.200" H - 10,000 per roll; Manufacturer: Brady; CompType: Label
Logo1 = CMP-0074838-1: Texas Instrument Corporate Signature; SymbolCreator: a0412235; Lib Reference: TI_Logo; Library Reference: Logo
Logo3 = CMP-0074847-1: FCC_disclaimer; Library Reference: Logo
ZZ1 = CMP-0003616-3
ZZ2 = CMP-0077236-1
ZZ3 = CMP-0077237-1
ZZ4 = CMP-0077238-1

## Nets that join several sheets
PGND: PD Controller (60 pins), Charger BQ25756 (48 pins)
I2C_SCL: PD Controller (J6.1 R10.2 R12.2 U8.6), Charger BQ25756 (R68.2)
I2C_SDA: PD Controller (J6.3 R11.2 R13.2 U8.5), Charger BQ25756 (R64.2)
LDO_3V3: PD Controller (14 pins), Charger BQ25756 (R67.1)
P5V0: PD Controller (8 pins), Charger BQ25756 (R72.1)
PPHV: PD Controller (8 pins), Charger BQ25756 (13 pins)
VBUS: PD Controller (8 pins), Charger BQ25756 (R59.1)

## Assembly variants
001: not fitted FID1 FID2 FID3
